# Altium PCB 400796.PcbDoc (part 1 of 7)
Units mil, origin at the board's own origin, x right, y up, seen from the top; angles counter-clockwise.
Board outline 2086.61 x 2086.61 mil, 6 copper layers (Top Layer, Mid Layer 1, Mid Layer 2, Mid Layer 3, Mid Layer 4, Bottom Layer), stack 58.818 mil thick; 313 components, 234 nets, 1244 pads, 2538 vias.
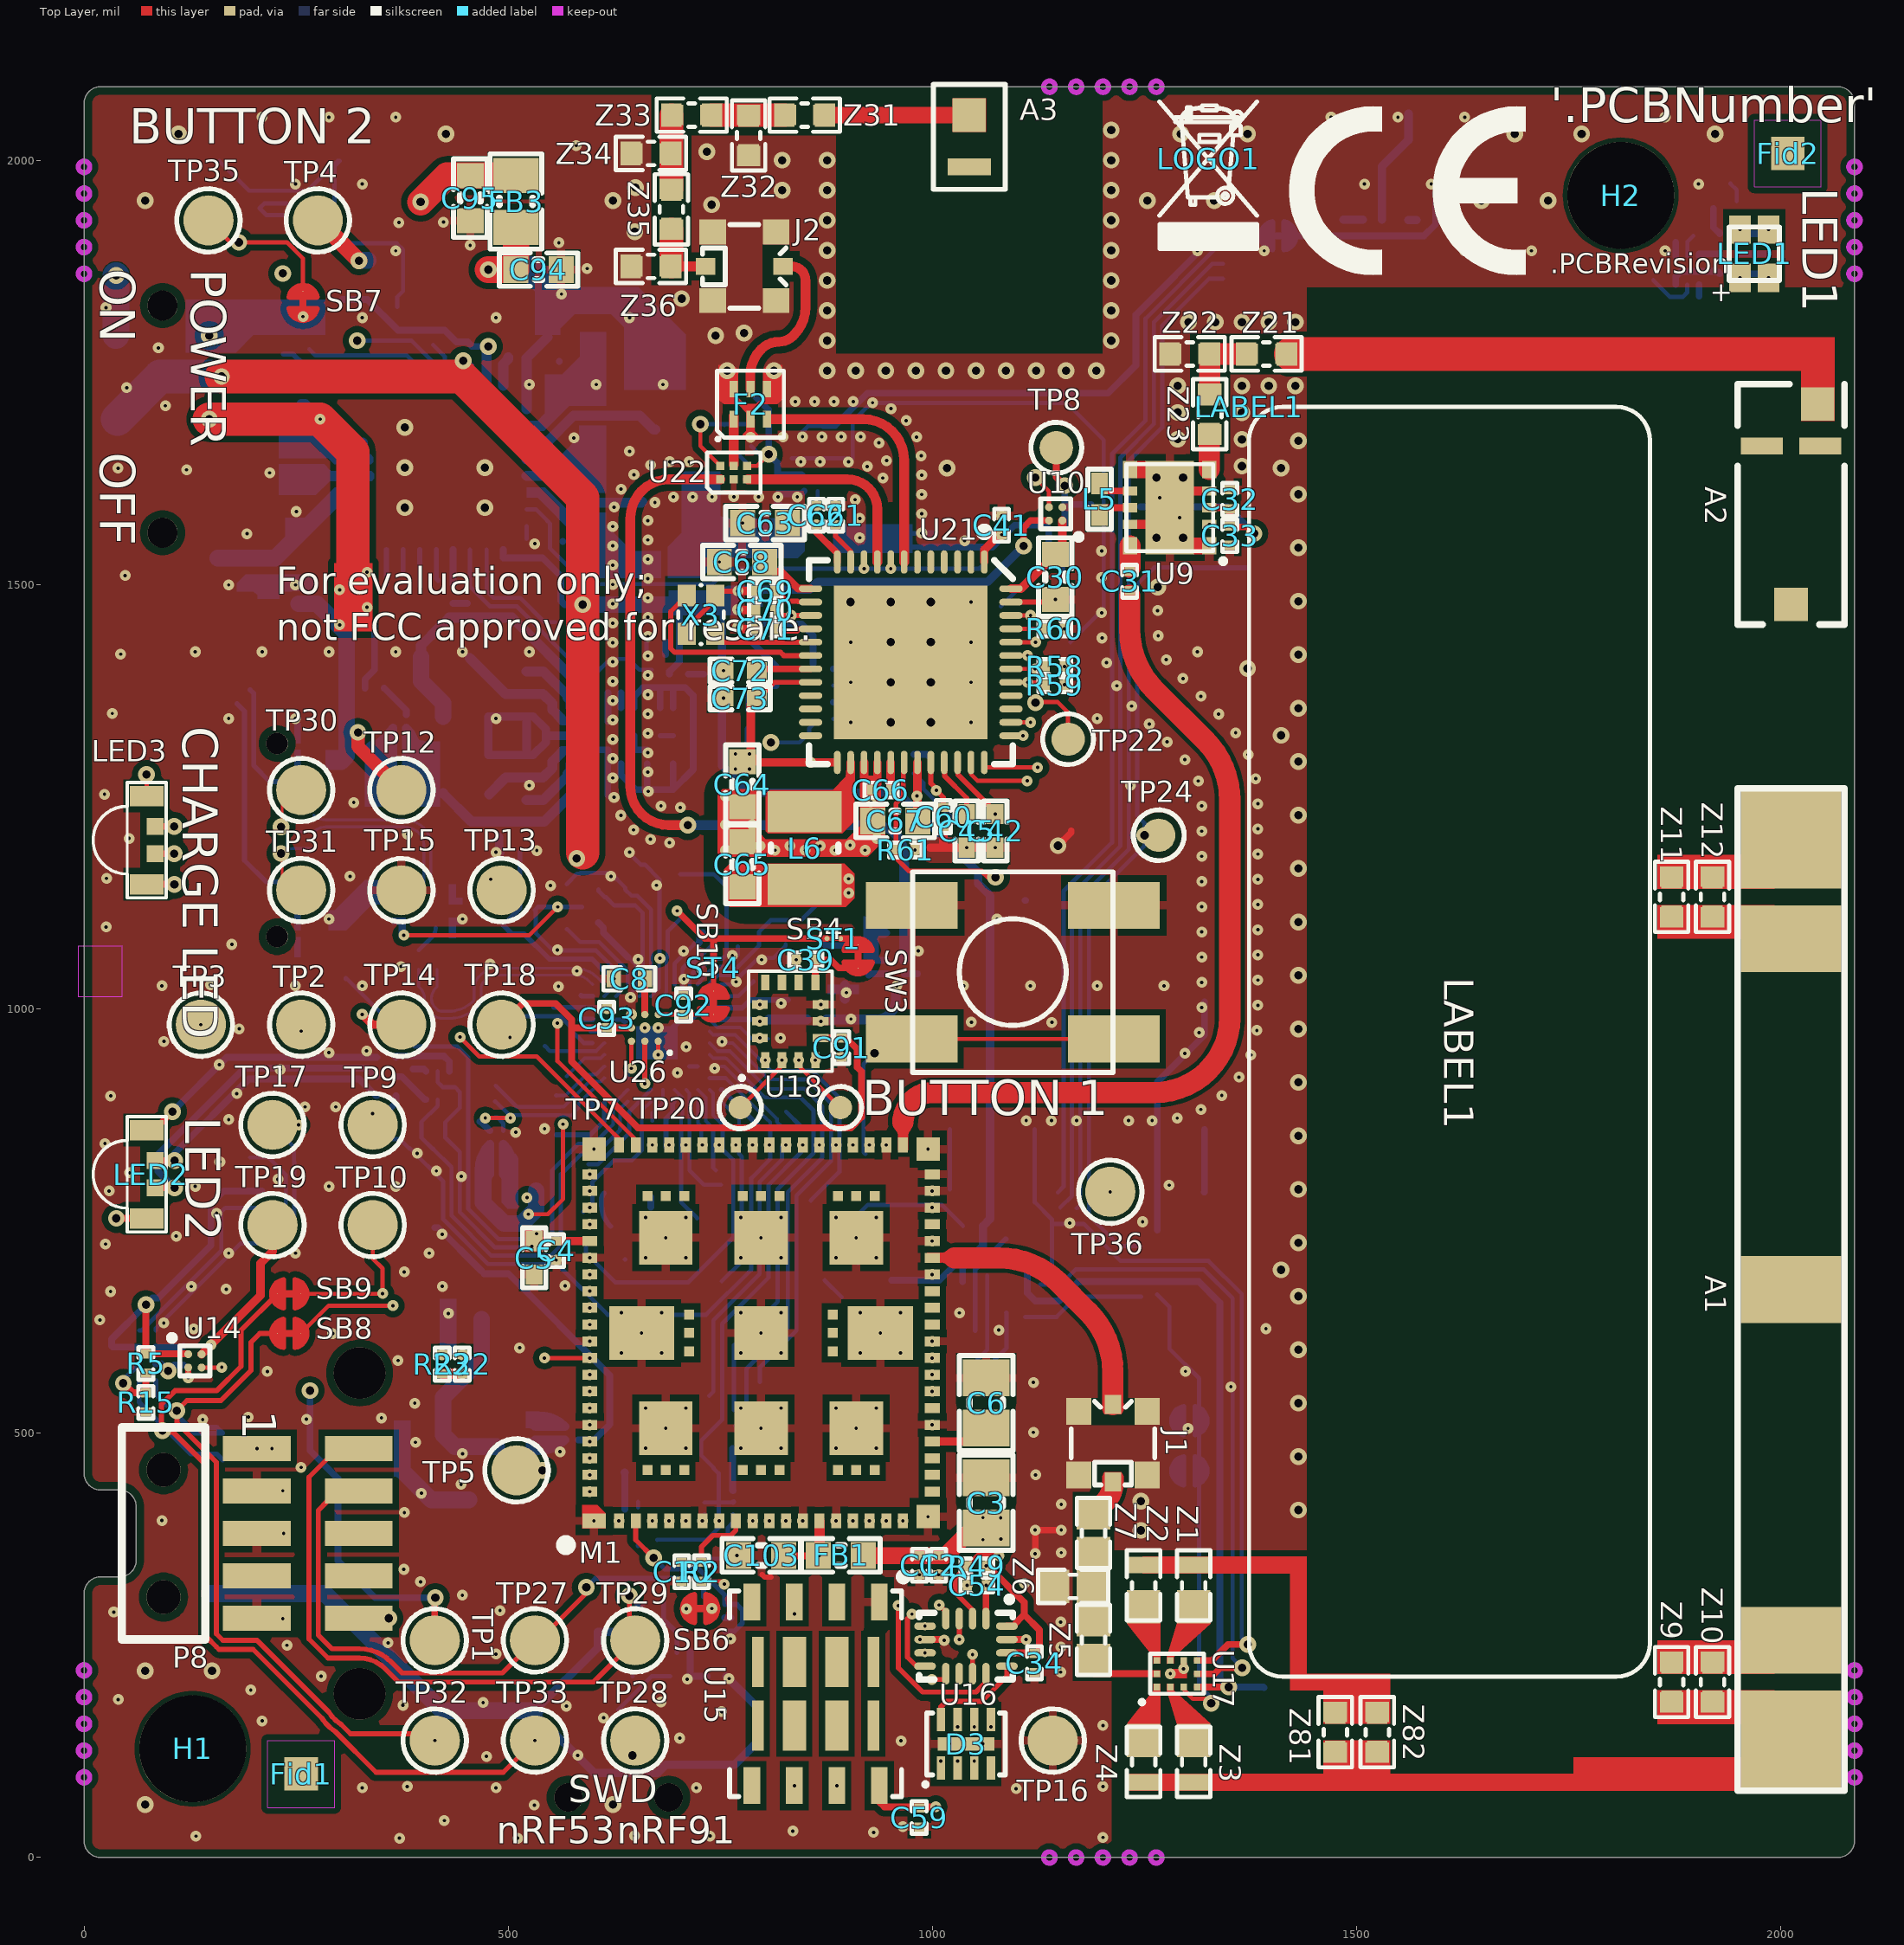
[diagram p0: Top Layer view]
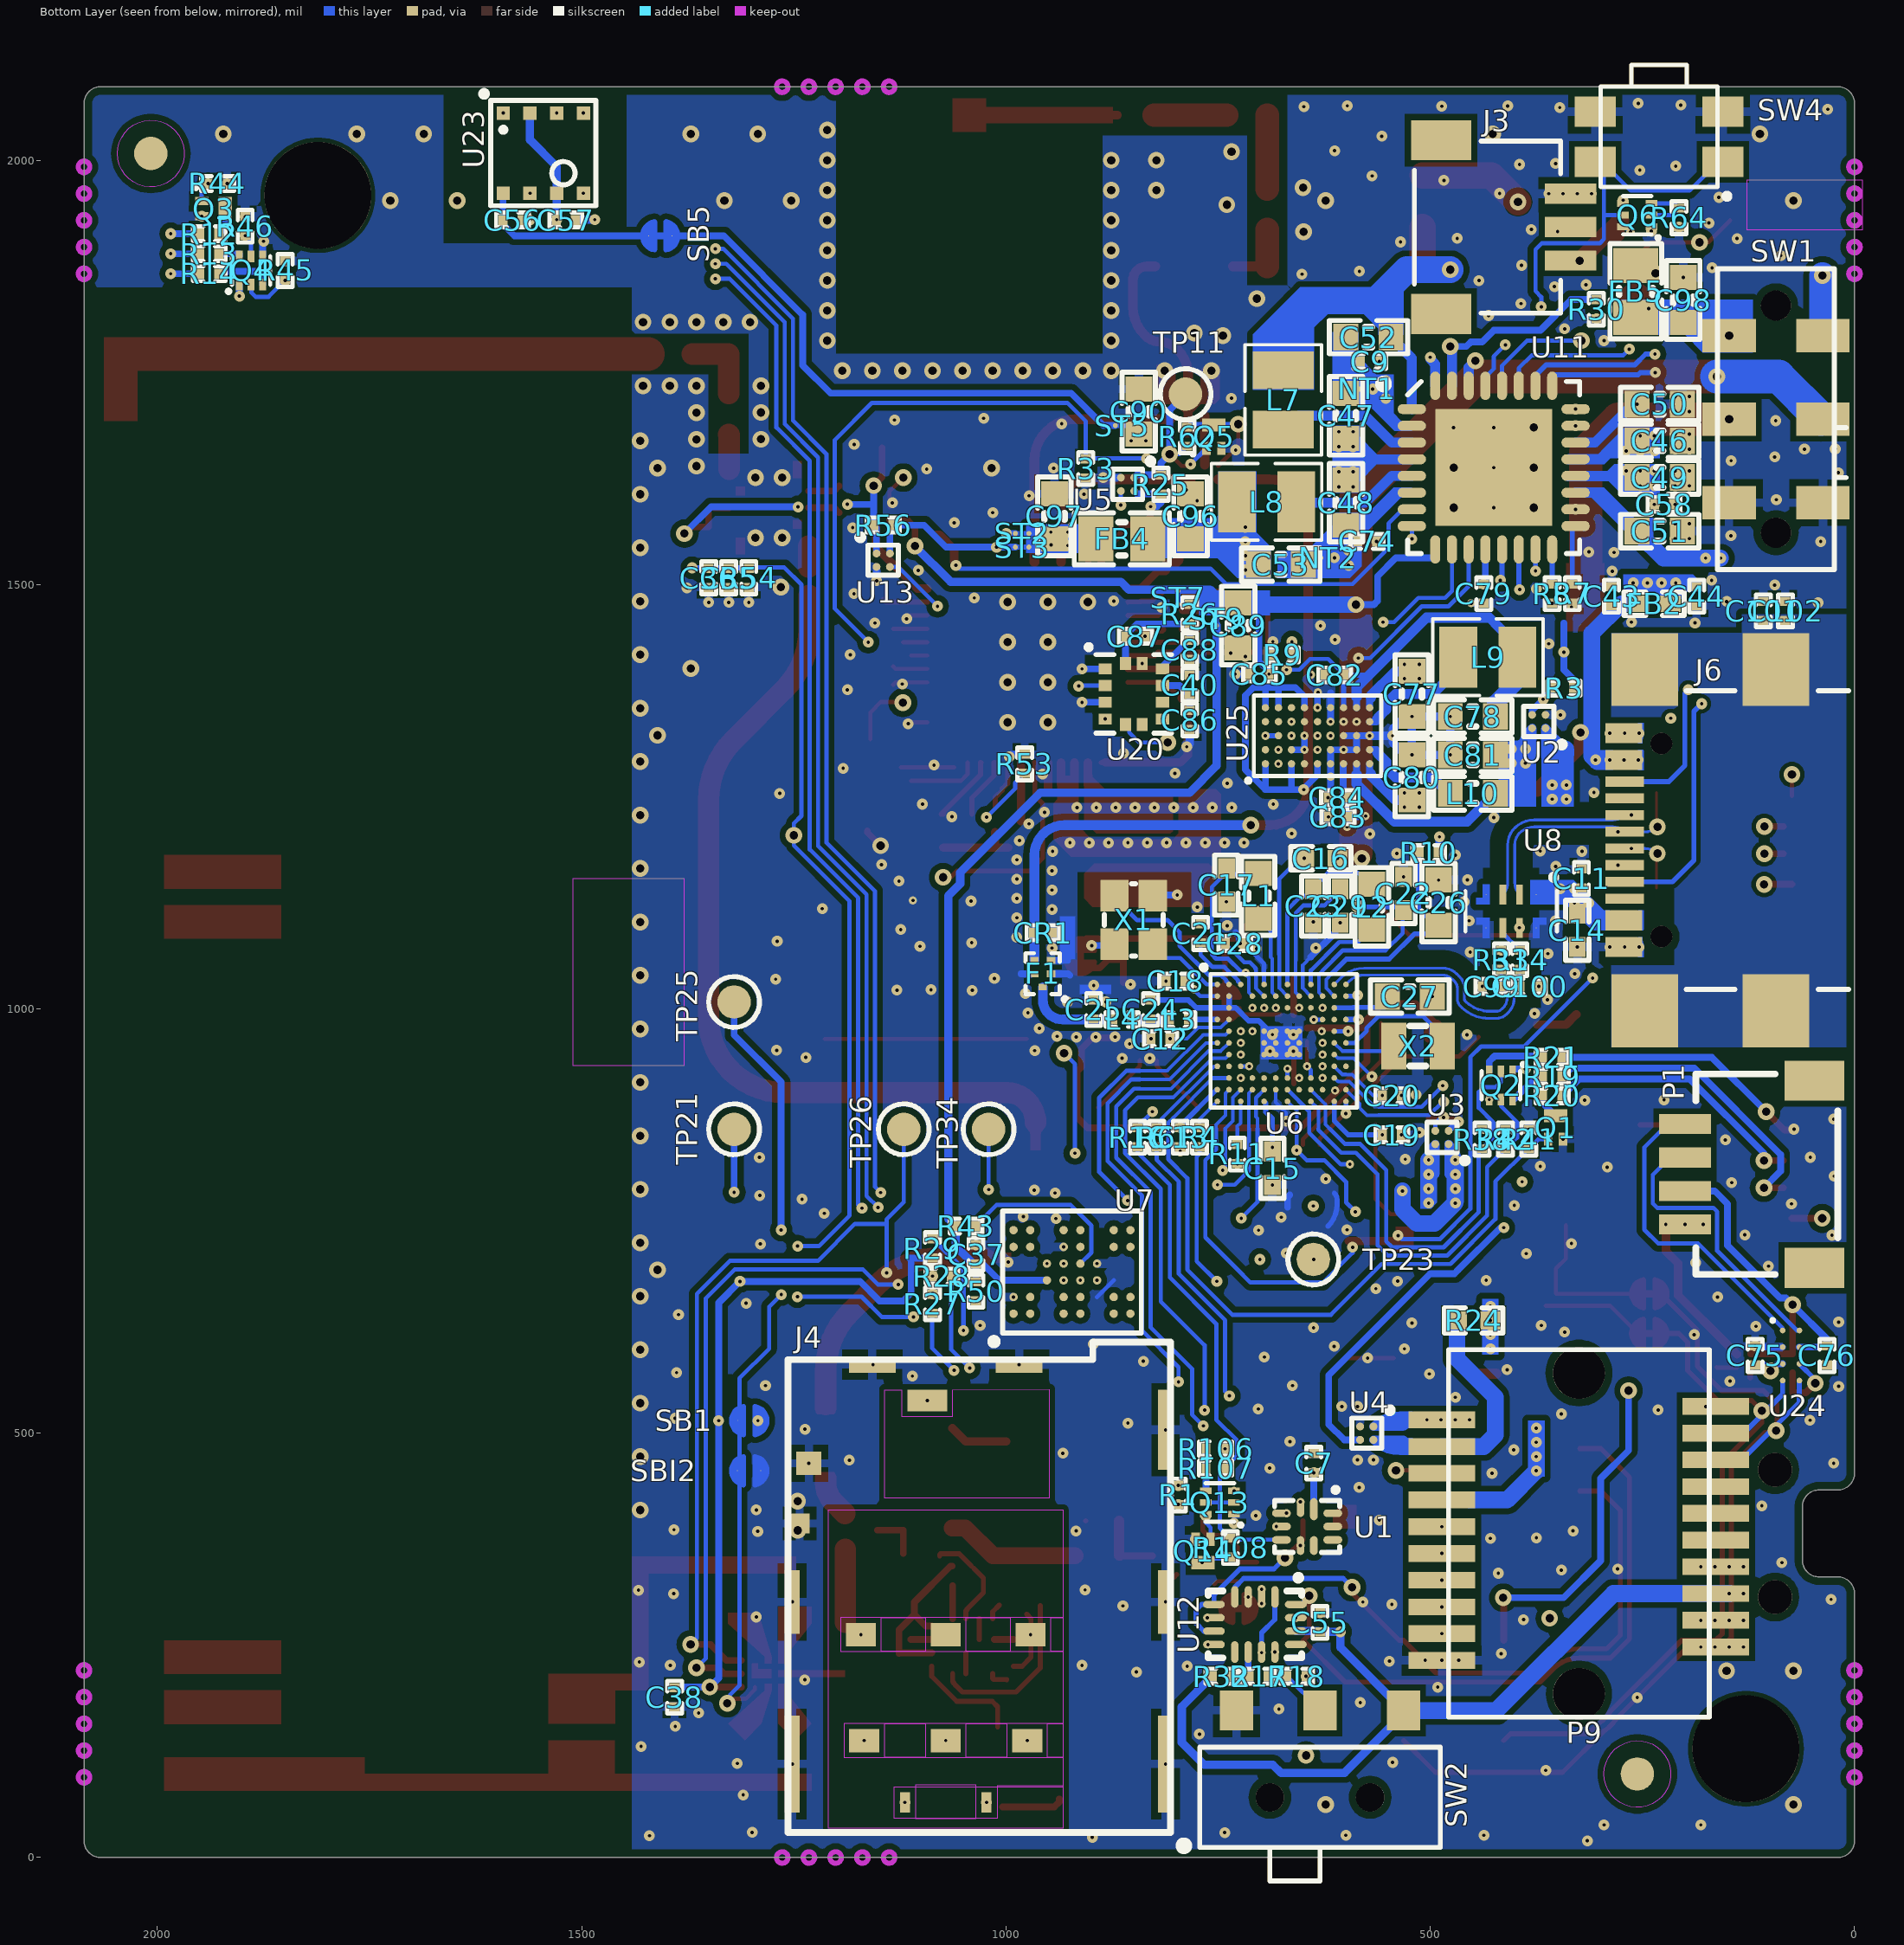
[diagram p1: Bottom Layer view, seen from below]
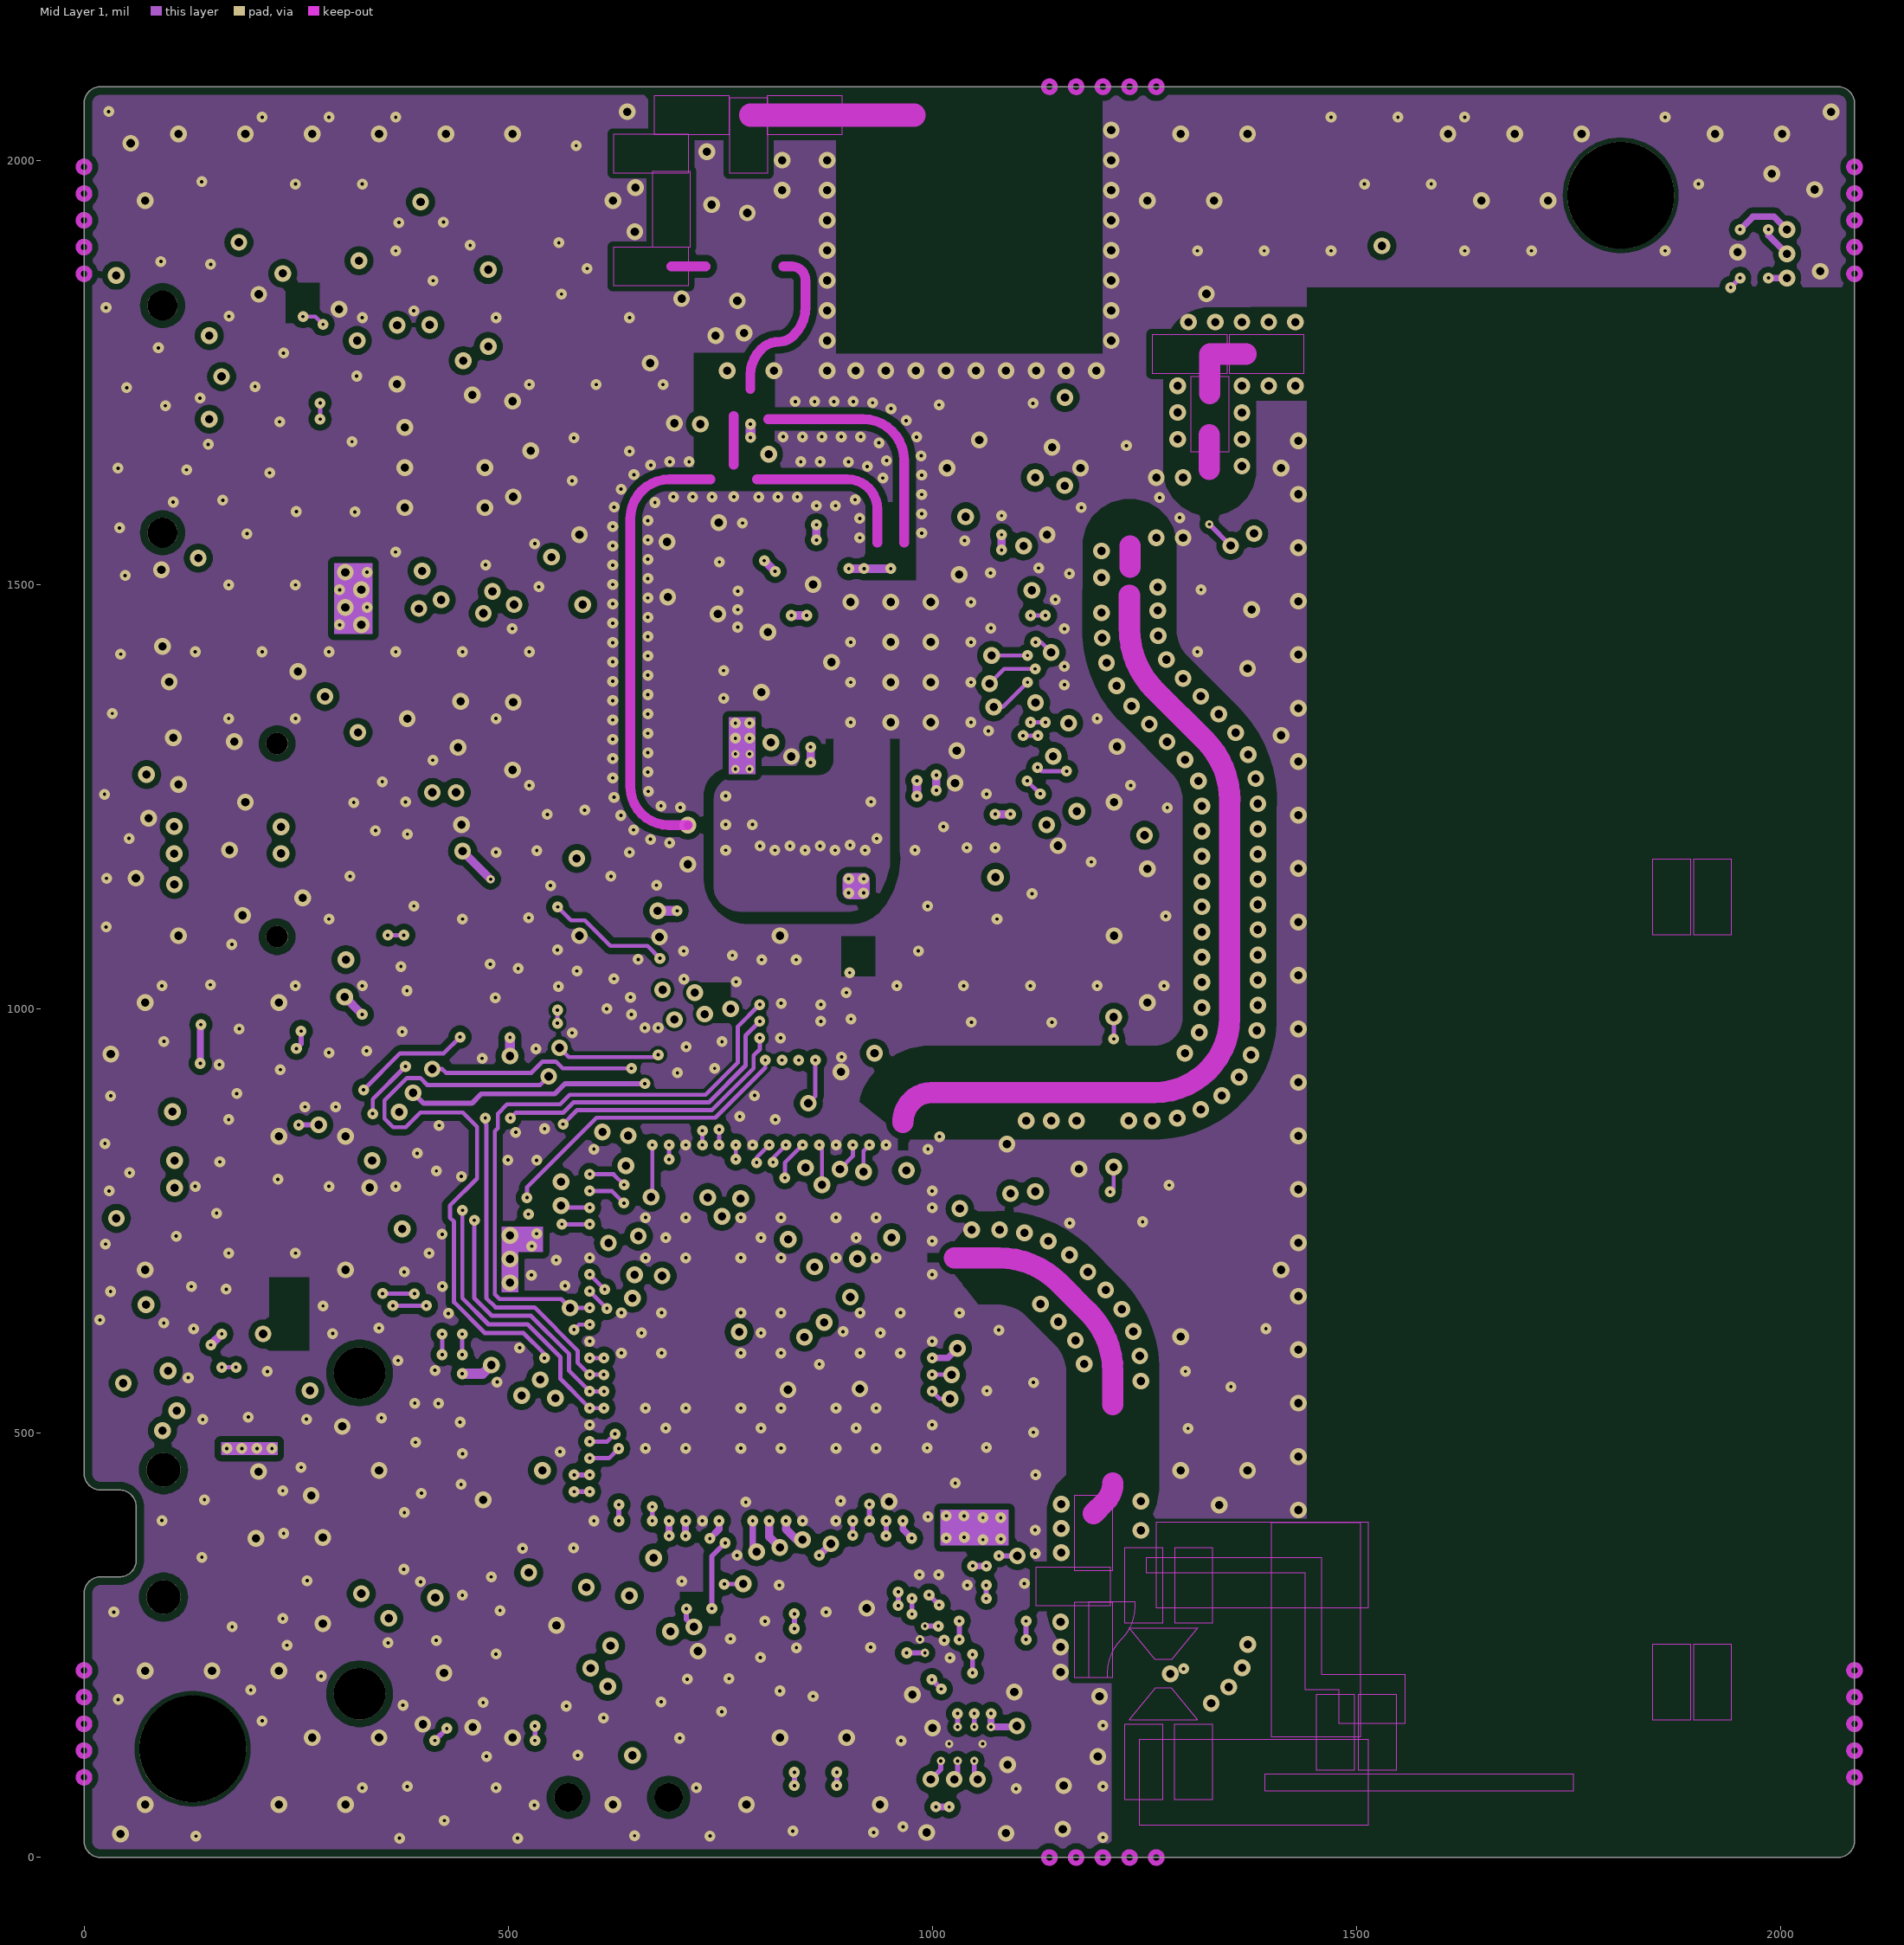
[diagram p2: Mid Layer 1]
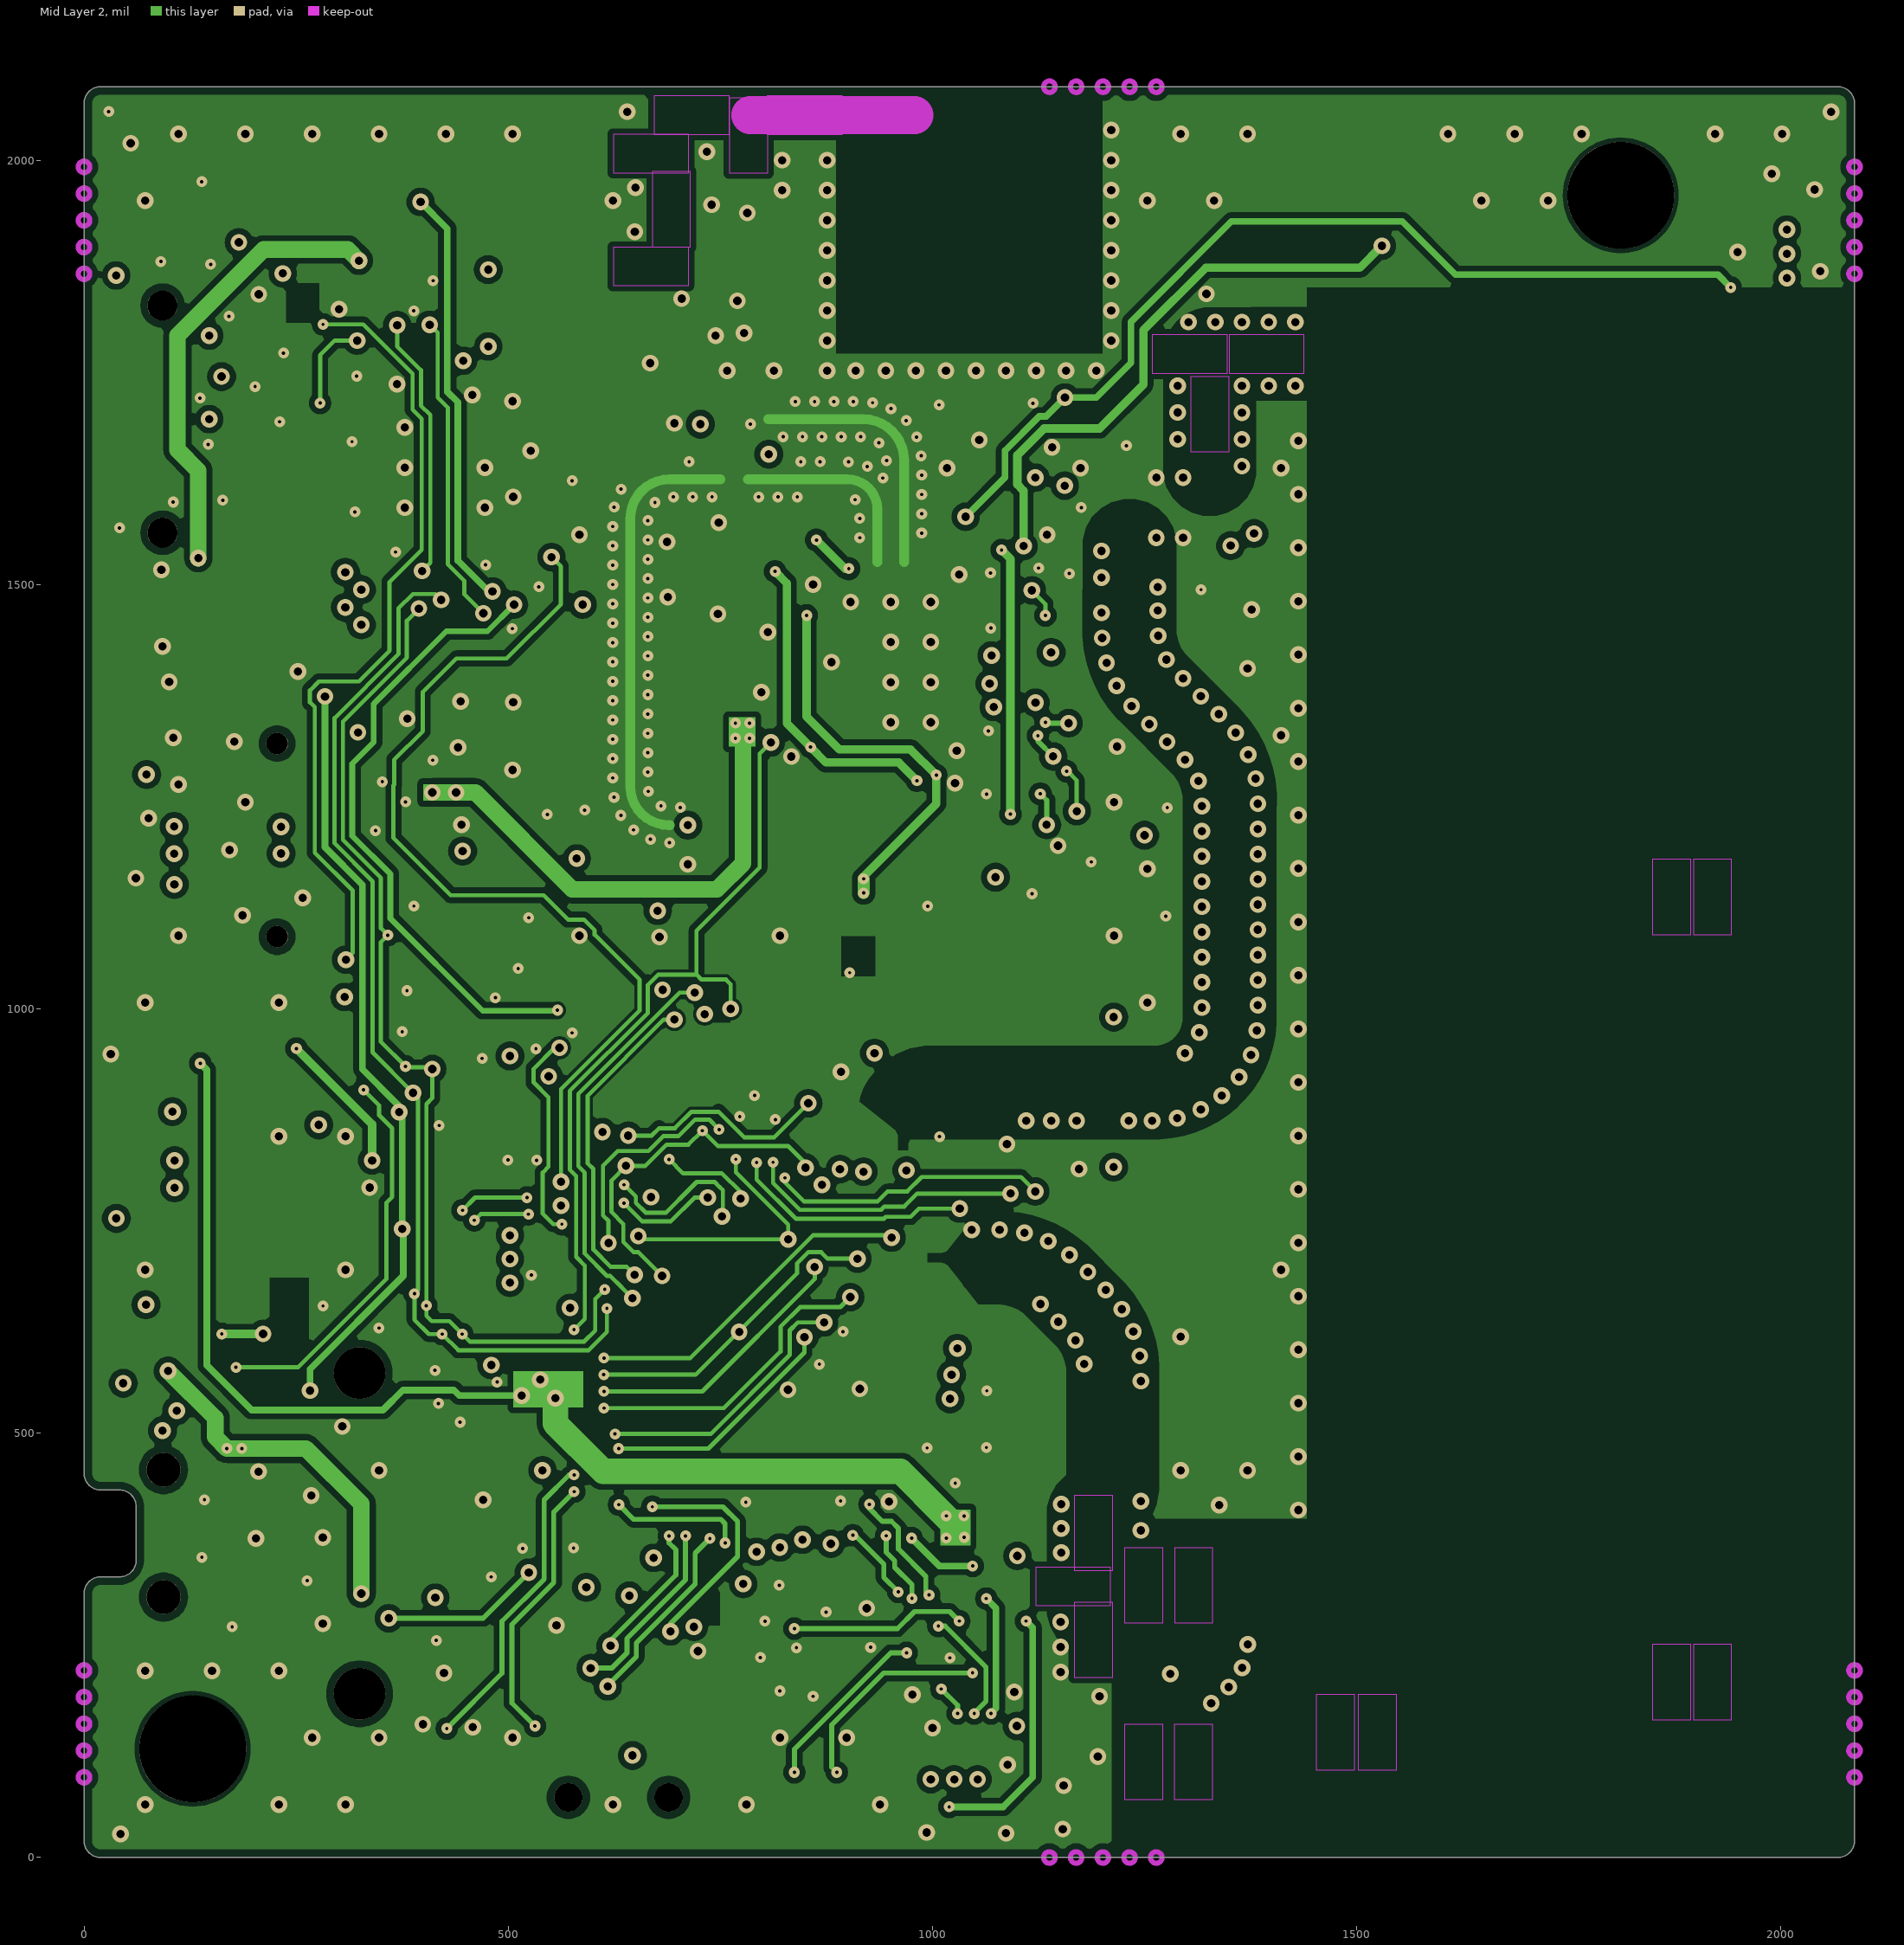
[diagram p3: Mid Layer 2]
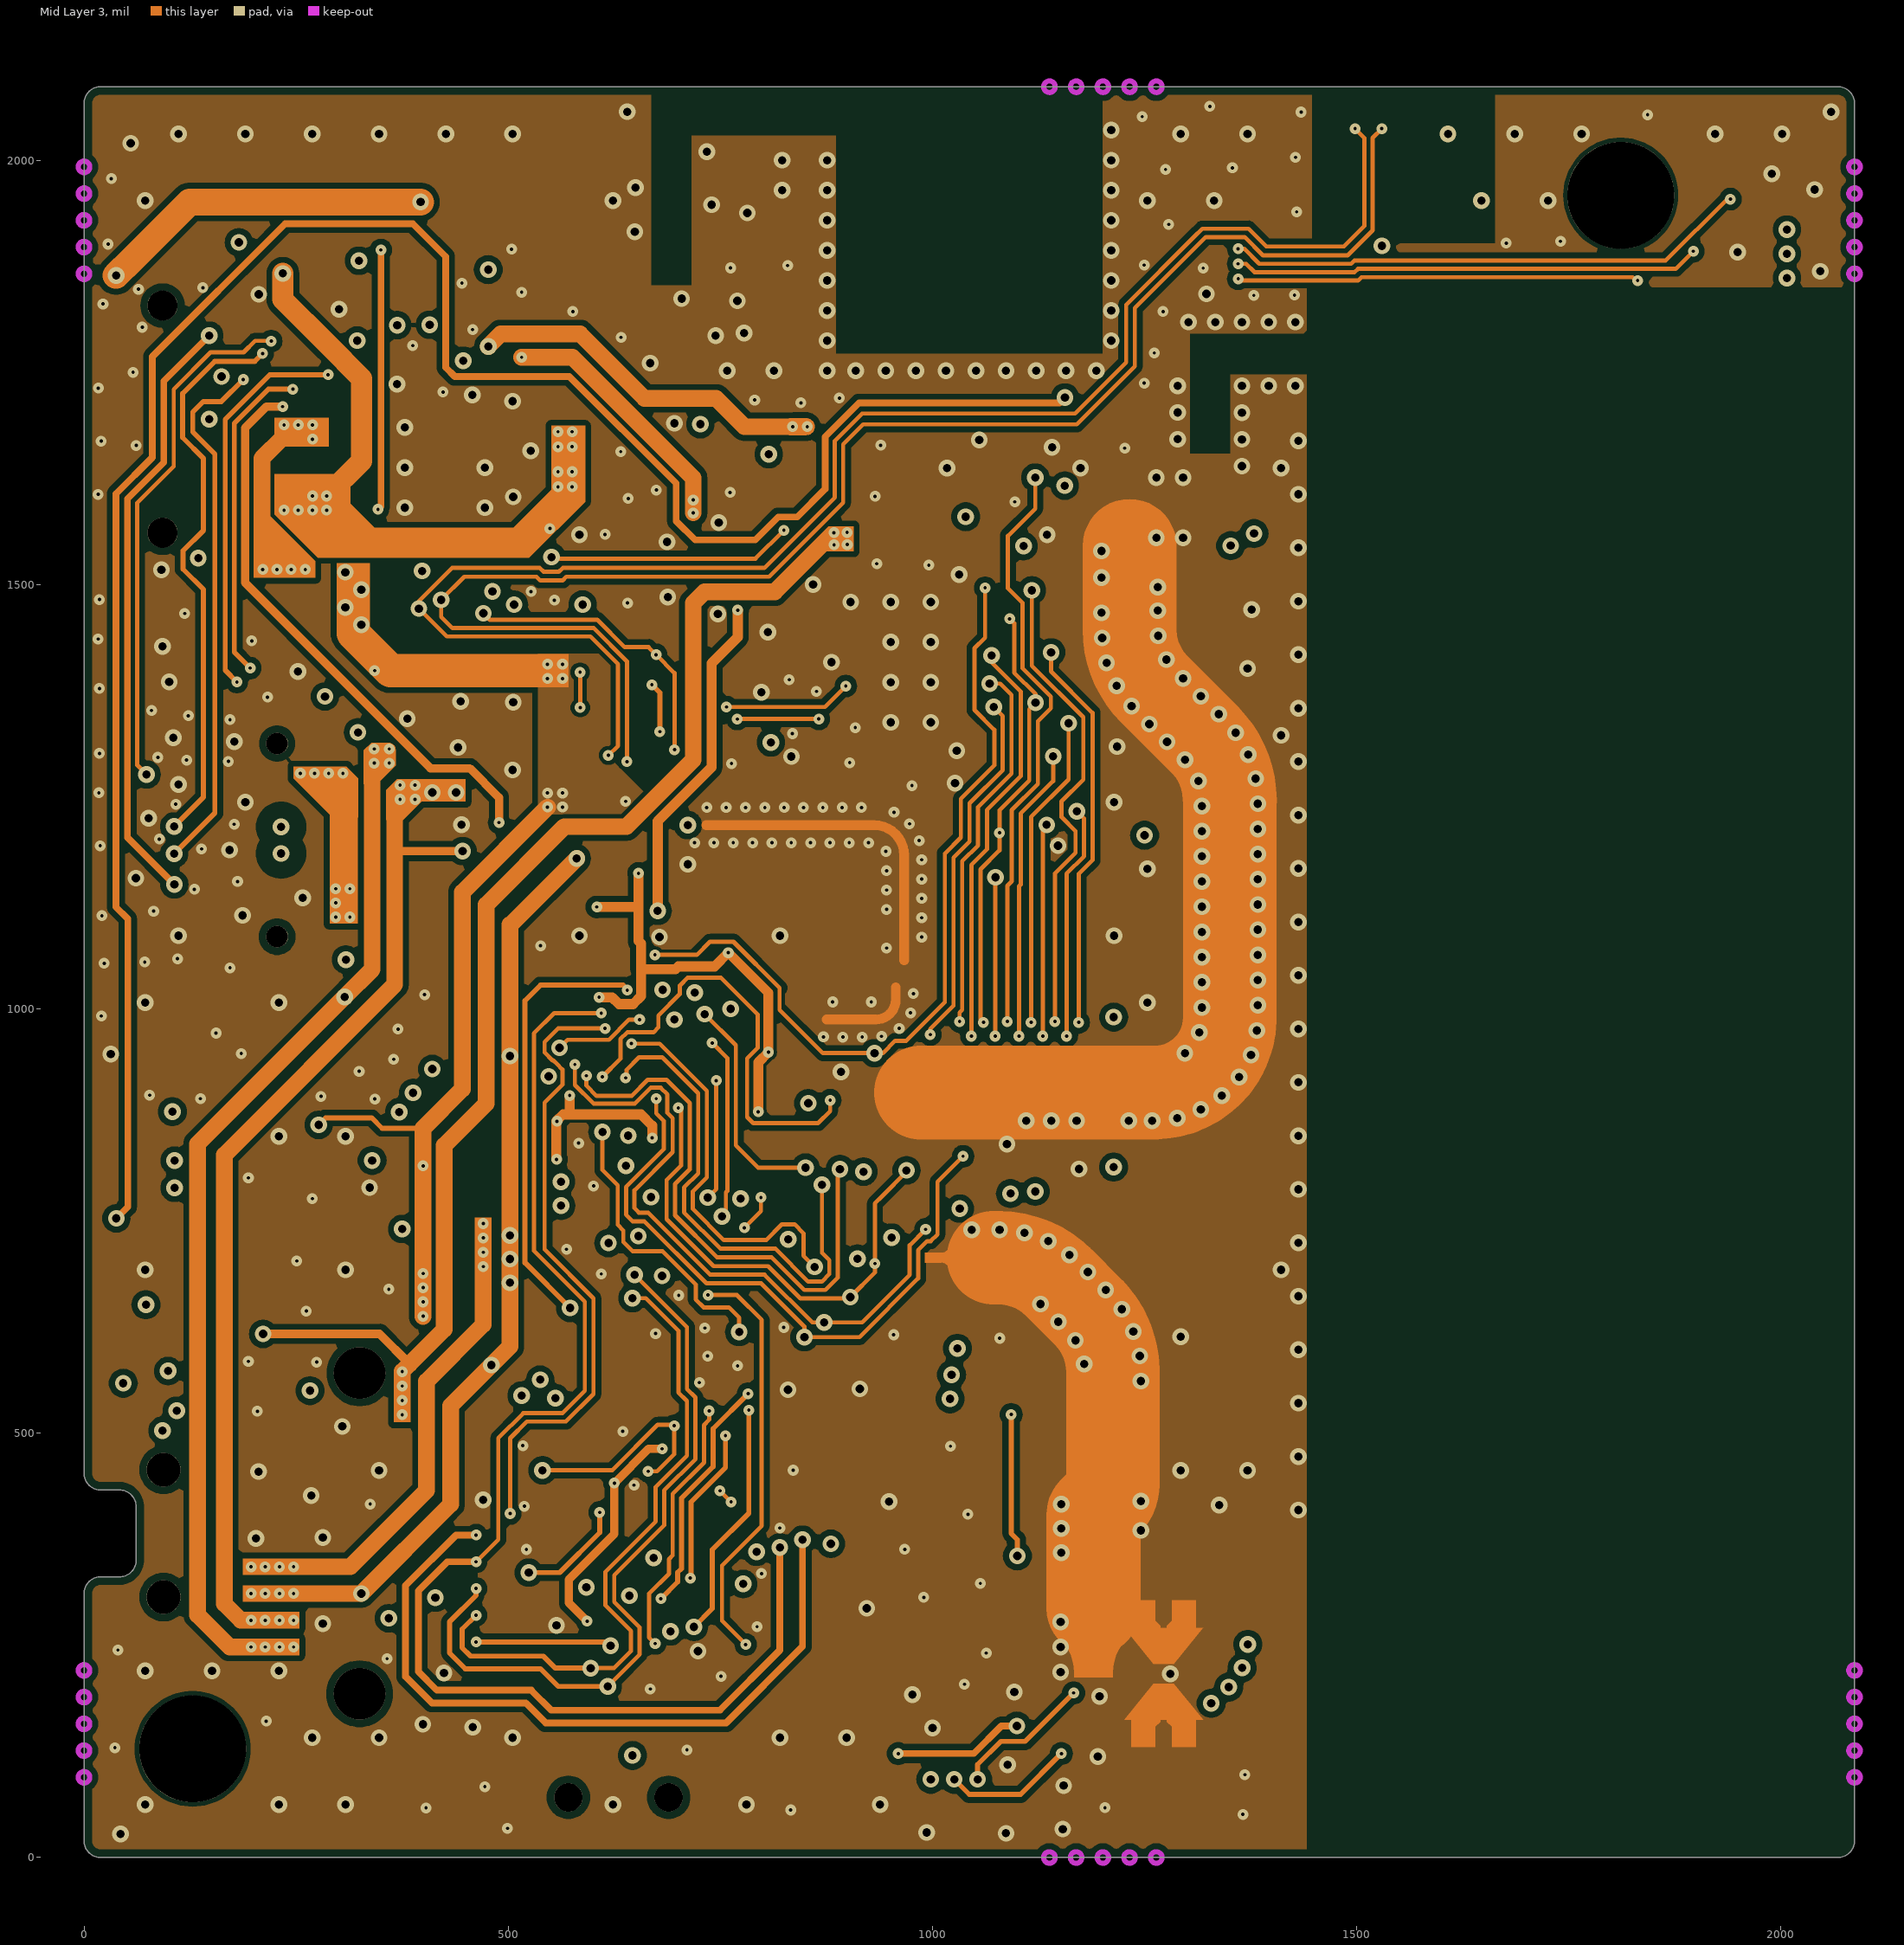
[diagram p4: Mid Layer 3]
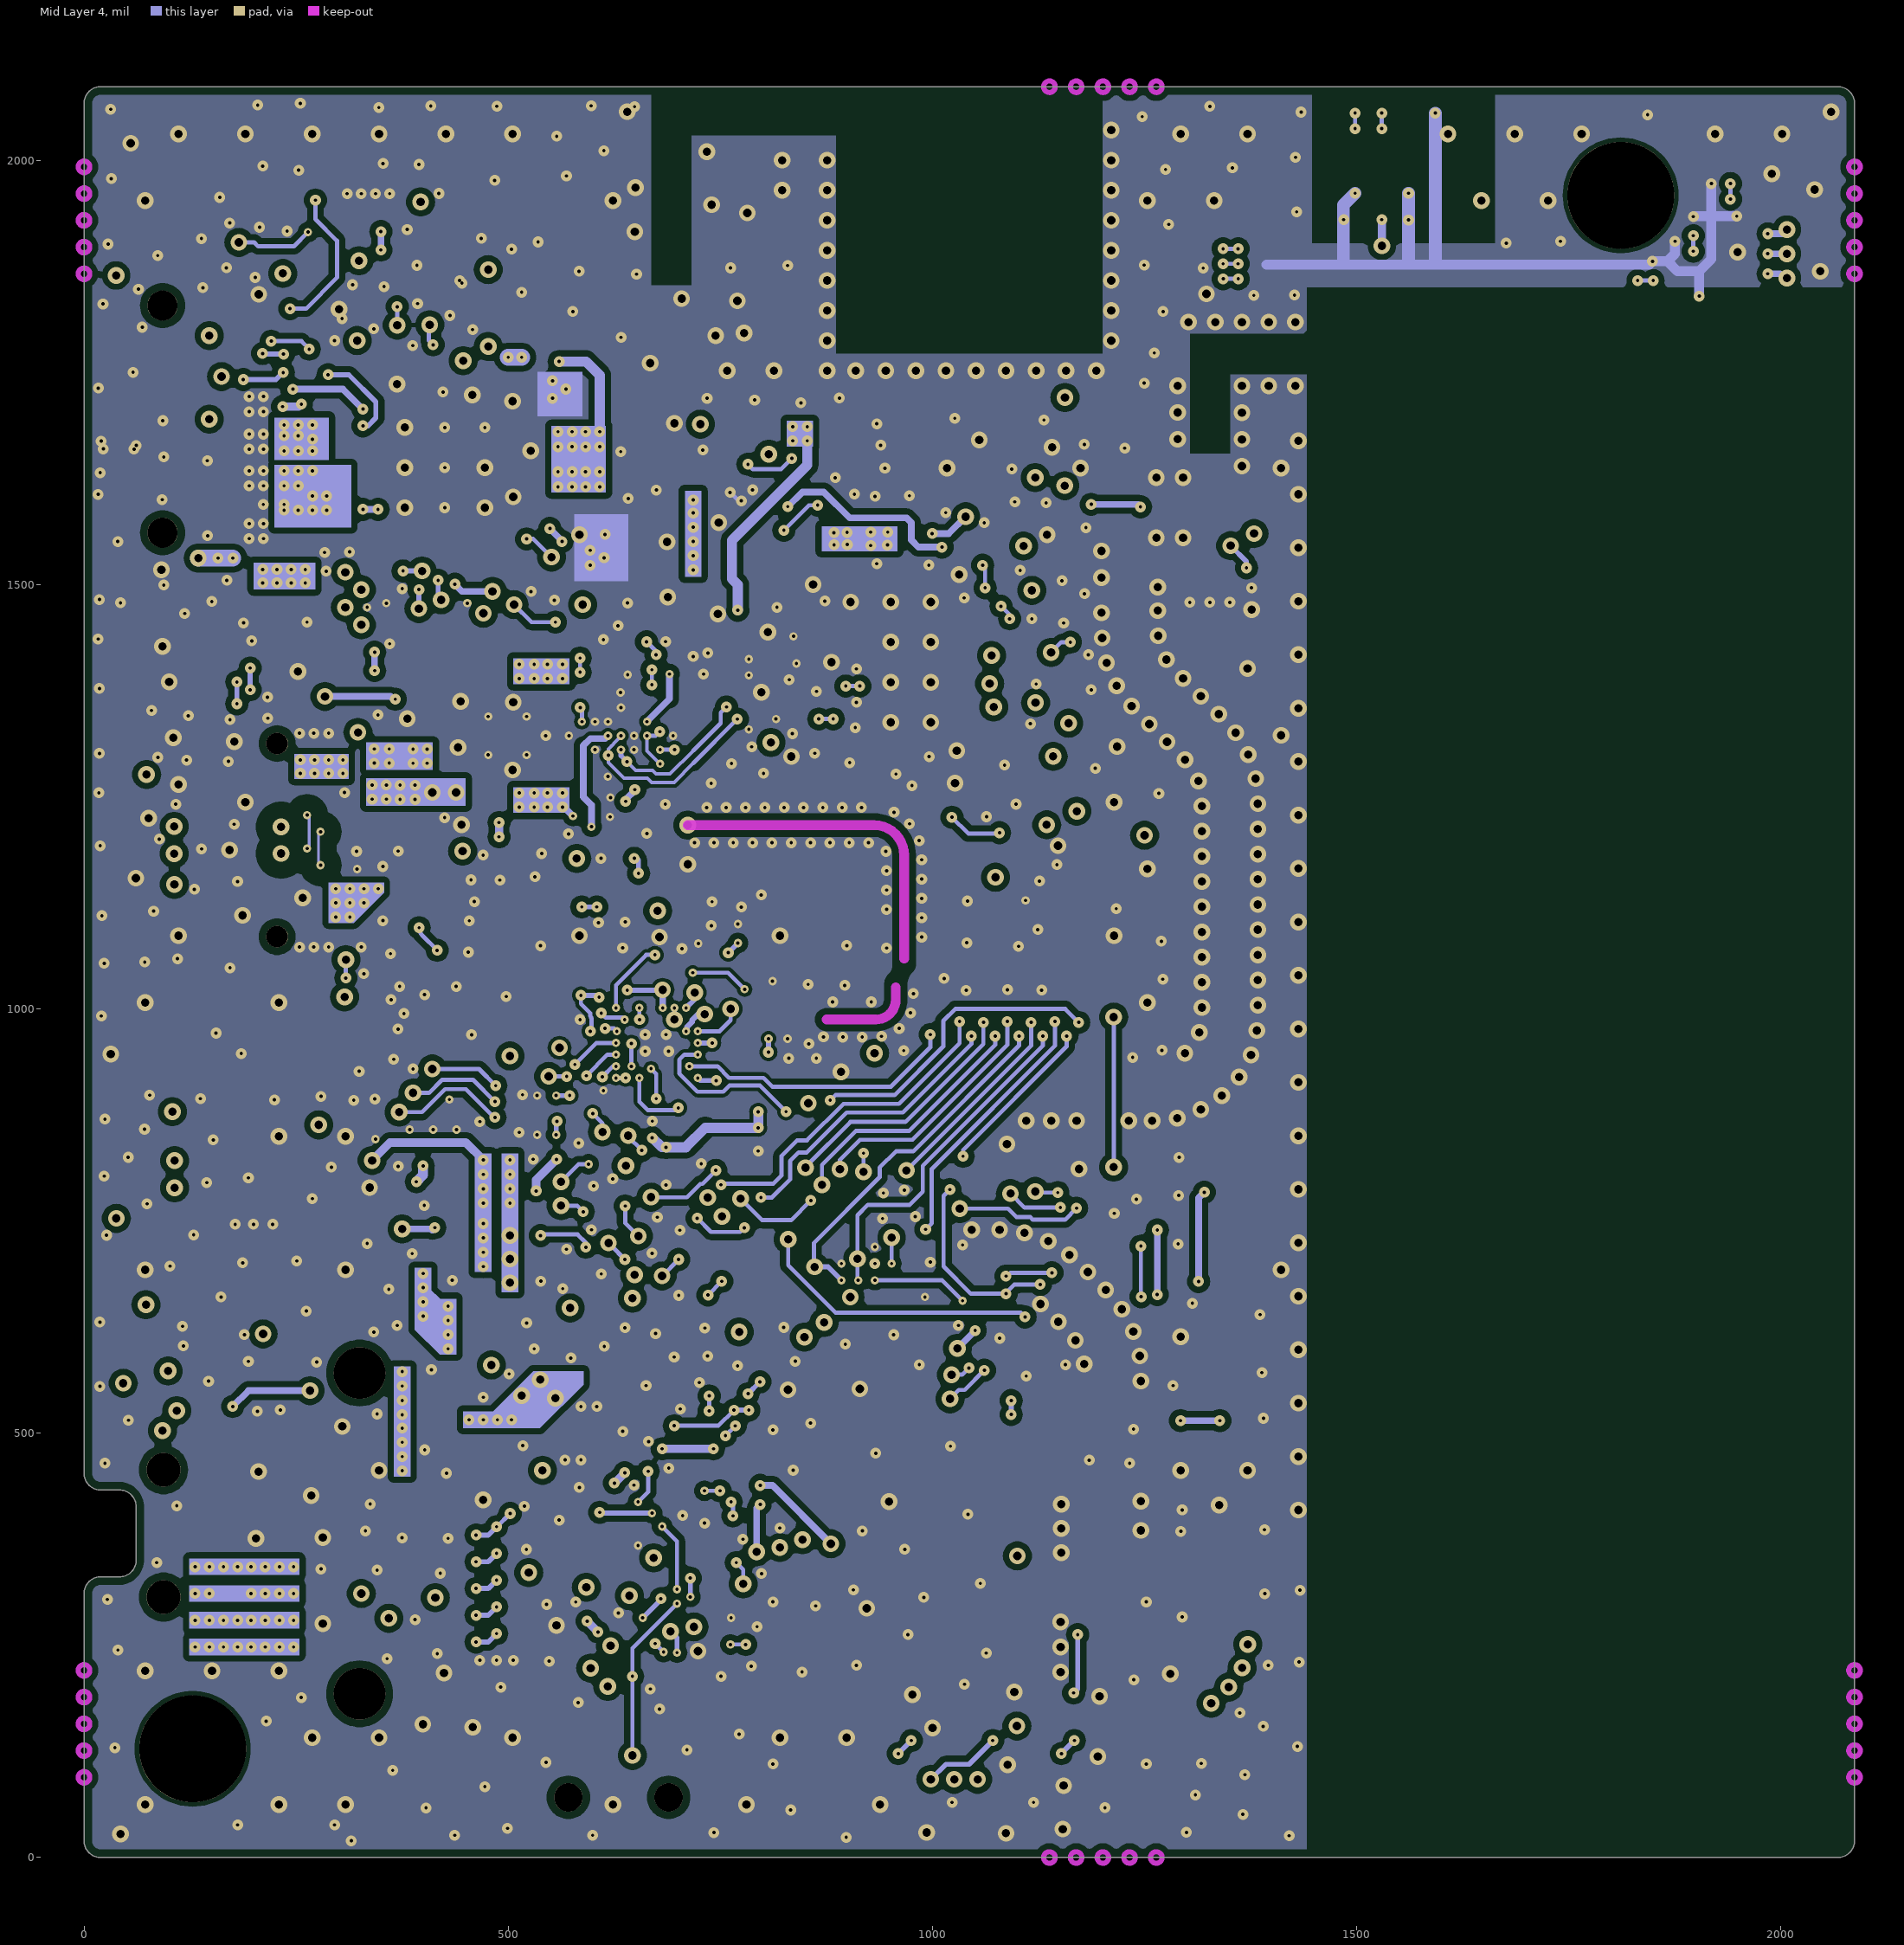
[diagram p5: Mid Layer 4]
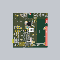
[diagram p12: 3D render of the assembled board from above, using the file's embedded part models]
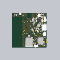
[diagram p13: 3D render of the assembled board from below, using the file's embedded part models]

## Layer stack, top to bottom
Top Solder: solder mask 1.969, Solder Resist Halogen-Free, Dk 3.5
Top Layer: signal copper 1.378
Dielectric1: prepreg 2.795, FR-4 Halogen-Free, Dk 4.2
Mid Layer 1: signal copper 1.378
Dielectric 3: prepreg 2.795, FR-4 Halogen-Free, Dk 4.2
Mid Layer 2: signal copper 1.378
Dielectric 2: core 39.37, Dk 4.51
Mid Layer 3: signal copper 1.378
Dielectric 1: prepreg 2.795, FR-4 Halogen-Free, Dk 4.2
Mid Layer 4: signal copper 1.378
Dielectric 4: prepreg 2.795, FR-4 Halogen-Free, Dk 4.2
Bottom Layer: signal copper 1.378
Bottom Solder: solder mask 1.969, Solder Resist Halogen-Free, Dk 3.5

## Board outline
0,19.69 ccw(c19.68,19.69) 19.68,0 2066.93,0 ccw(c2066.93,19.69) 2086.61,19.69 2086.61,2066.93 ccw(c2066.93,2066.93) 2066.93,2086.61 19.68,2086.61 ccw(c19.68,2066.93) 0,2066.93 0,452.75 ccw(c19.68,452.75) 19.68,433.07 41.73,433.07 cw(c41.73,413.38) 61.42,413.38 61.42,350.39 cw(c41.73,350.39) 41.73,330.71 19.69,330.71 ccw(c19.69,311.02) 0,311.02

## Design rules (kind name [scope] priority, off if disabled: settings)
BoardOutlineClearance BoardOutlineClearance_Power_SW [HasFootprint('Switch-Slide-RA-J-Lead-DPDT-8.5x3.5mm')] p1: gap=5.91 ignorepadtopadclearanceinfootprint=FALSE
BoardOutlineClearance [(OnLayer('Top Layer') or OnLayer('Bottom Layer') or OnLayer('Mid Layer 1') or OnLayer('Mid Layer 2') or OnLayer('Mid Layer 3') or OnLayer('Mid Layer 4')) and not Keepout] p2: gap=9.45 ignorepadtopadclearanceinfootprint=FALSE
Clearance Clearance_NPTH [InPadClass('NPTH')] p1: gap=5 ignorepadtopadclearanceinfootprint=FALSE
Clearance "Schematic Clearance Constraint_1" [InComponent('H2')] p2: gap=10 ignorepadtopadclearanceinfootprint=TRUE except(0: Arc-Hole Track-Hole SMDPad-Hole THPad-Hole Via-Hole Fill-Hole Poly-Hole Region-Hole Text-Hole)
Clearance "Schematic Clearance Constraint" [InComponent('H1')] p3: gap=10 ignorepadtopadclearanceinfootprint=TRUE except(0: Arc-Hole Track-Hole SMDPad-Hole THPad-Hole Via-Hole Fill-Hole Poly-Hole Region-Hole Text-Hole)
Clearance "Stitching GND blind" [IsStitchingVia and (InDrillLayerPair('Top Layer - Mid Layer 1') or InDrillLayerPair('Mid Layer 4 - Bottom Layer')) and InNet('GND') vs (IsVia and InDrillLayerPair('Top Layer - Bottom Layer')) Or IsPad] p4: gap=39.37 ignorepadtopadclearanceinfootprint=FALSE
Clearance "Stitching GND" [IsStitchingVia and InNet('GND') vs IsVia Or IsPad] p5: gap=9.84 ignorepadtopadclearanceinfootprint=FALSE
Clearance Clearance_nRF5340 [All vs WithinRoom('nRF53')] p6: gap=3.94 ignorepadtopadclearanceinfootprint=FALSE
Clearance Clearance_nPM6001 [OnLayer('Mid Layer 4') vs WithinRoom('nPM6001')] p7: gap=4.13 ignorepadtopadclearanceinfootprint=FALSE
Clearance USB_Poly_Clearance [(InNamedPolygon('Top Layer-GND')) or (InNamedPolygon('Mid_Layer_1_Codec-GND')) or (InNamedPolygon('Mid_Layer_3-GND')) or (InNamedPolygon('Mid_Layer_3-GND')) or (InNamedPolygon('Mid_Layer_4-GND')) or (InNamedPolygon('Mid_Layer_1-AGND') or InNamedPolygon('Bottom_Layer-GND')) vs InAnyDifferentialPair] p8: gap=19.68 ignorepadtopadclearanceinfootprint=FALSE
Clearance "Diff_Pair_Clearance_Other _Diffpair" [InAnyDifferentialPair and (IsArc or IsTrack)] p9: gap=11.8 ignorepadtopadclearanceinfootprint=FALSE
Clearance Diff_Pair_Clearance_Not_Diffpair [InAnyDifferentialPair and (IsArc or IsTrack) vs not InAnyDifferentialPair] p10: gap=4.92 ignorepadtopadclearanceinfootprint=FALSE
Clearance Microvia_Clearance [AsMM(ViaDiameter) = 0.3 vs AsMM(ViaDiameter) = 0.3] p11: gap=3.94 ignorepadtopadclearanceinfootprint=FALSE
Clearance "NPTH clearance_MIC" [(Not PadIsPlated And HoleSize > 0) and (InRegionRelative(100,1032,150,1092) or InRegionRelative(1000,1952,1050,2002))] p12: gap=3.94 ignorepadtopadclearanceinfootprint=FALSE
Clearance "NPTH clearance" [Not PadIsPlated And HoleSize > 0] p13: gap=8.66 ignorepadtopadclearanceinfootprint=FALSE
Clearance RF_Clerance [InNetClass('RF')] p14: gap=4.92 ignorepadtopadclearanceinfootprint=FALSE
Clearance RF_Clerance_RF_BLE/WIFI [InNetClass('RF_BLE/WIFI') vs InNamedPolygon('Top_Layer-GND') or InNamedPolygon('Bottom_Layer-GND')] p15: gap=7.87 ignorepadtopadclearanceinfootprint=FALSE
Clearance Polygon_Clearance_Codec [InNamedPolygon('Mid_Layer_1_Codec-GND')] p16: gap=4.92 ignorepadtopadclearanceinfootprint=FALSE
Clearance Polygon_Clearance [(InNamedPolygon('Top_Layer-GND')) or (InNamedPolygon('Mid_Layer_1-GND')) or (InNamedPolygon('Mid_Layer_2-GND')) or (InNamedPolygon('Mid_Layer_3-GND')) or (InNamedPolygon('Mid_Layer_4-GND')) or (InNamedPolygon('Mid_Layer_4-AGND') or InNamedPolygon('Bottom_Layer-GND'))] p17: gap=7.09 ignorepadtopadclearanceinfootprint=FALSE
Clearance [All] p18: gap=4.92 ignorepadtopadclearanceinfootprint=FALSE
ComponentClearance [All] p1 off: gap=10 collisioncheckmode=3 verticalgap=10 showdistances=FALSE
DiffPairsRouting [InAnyDifferentialPair] p1: maxlimit=5 minlimit=5 mostfreqgap=5 toplayer_minwidth=3.27 toplayer_maxwidth=3.27 toplayer_prefwidth=3.27 midlayer1_minwidth=1.63 midlayer1_maxwidth=1.63 midlayer1_prefwidth=1.63 midlayer2_minwidth=2.31 midlayer2_maxwidth=2.31 midlayer2_prefwidth=2.31 midlayer3_minwidth=2.31 midlayer3_maxwidth=2.31 midlayer3_prefwidth=2.31 midlayer4_minwidth=1.63 midlayer4_maxwidth=1.63 midlayer4_prefwidth=1.63 bottomlayer_minwidth=3.27 bottomlayer_maxwidth=3.27 bottomlayer_prefwidth=3.27 impedanceprofiledriven=TRUE impedanceprofileid={B73BED5C-2360-4F1A-9E9C-C8917F192C1F} impedanceprofilevalue=90.000000 maxuncoupledlength=500
FabricationTestPointUsage TestPointUsage [All] p1: valid=0 allowmultiple=FALSE
FabricationTestpoint Testpoint [All] p1: side=3 testpointundercomponent=TRUE minsize=40 maxsize=100 preferedsize=60 minholesize=0 maxholesize=40 preferedholesize=32 testpointgrid=1 allowsidetop=TRUE allowsidebottom=TRUE usegrid=TRUE gridtolerance=0.01
Height [All] p1 off: minheight=0 maxheight=1000 prefheight=500
HoleSize HoleSize_Laser_Via [IsVia and (InDrillLayerPair('Top Layer - Mid Layer 1') or InDrillLayerPair('Mid Layer 1 - Mid Layer 2') or InDrillLayerPair('Mid Layer 3 - Mid-Layer 4') or InDrillLayerPair('Mid Layer 4 - Bottom Layer'))] p1: absolutevalues=TRUE maxlimit=3.94 minlimit=3.94 maxpercent=80.000 minpercent=20.000
HoleSize HoleSize_Mech_Via [IsVia and (InDrillLayerPair('Top Layer - Bottom Layer') or InDrillLayerPair('Mid Layer 1 - Mid Layer 4'))] p2: absolutevalues=TRUE maxlimit=9.84 minlimit=9.84 maxpercent=80.000 minpercent=20.000
HoleSize [All] p3: absolutevalues=TRUE maxlimit=196.85 minlimit=3.94 maxpercent=80.000 minpercent=20.000
HoleToHoleClearance HoleToHoleClearance_PMIC [InDrillLayerPair('Mid Layer 4 - Bottom Layer') and InRegionRelative(580,1280,700,1350) vs InDrillLayerPair('Mid Layer 4 - Bottom Layer') and InRegionRelative(580,1280,700,1350)] p1: gap=11.42 allowstackedmicrovias=FALSE
HoleToHoleClearance HoleToHoleClearance_T-B_T-B [InDrillLayerPair('Top Layer - Bottom Layer') vs InDrillLayerPair('Top Layer - Bottom Layer')] p2 off: gap=17.72 allowstackedmicrovias=FALSE
HoleToHoleClearance HoleToHoleClearance_TH-TH [AsMM(ViaDiameter) = 0.50 vs AsMM(ViaDiameter) = 0.50] p3: gap=17.72 allowstackedmicrovias=FALSE
HoleToHoleClearance HoleToHoleClearance_TH-Micro [AsMM(ViaDiameter) = 0.50 vs AsMM(ViaDiameter) = 0.30] p4: gap=17.72 allowstackedmicrovias=FALSE
HoleToHoleClearance HoleToHoleClearance_Micro-Micro [AsMM(ViaDiameter) = 0.32 vs AsMM(ViaDiameter) = 0.32] p5: gap=11.81 allowstackedmicrovias=FALSE
HoleToHoleClearance HoleToHoleClearance_T-B_M1-M4 [InDrillLayerPair('Top Layer - Bottom Layer') vs InDrillLayerPair('Mid Layer 1 - Mid Layer 4')] p6 off: gap=17.72 allowstackedmicrovias=FALSE
HoleToHoleClearance HoleToHoleClearance_T-B_T-M1 [InDrillLayerPair('Top Layer - Bottom Layer') vs InDrillLayerPair('Top Layer - Mid Layer 1')] p7 off: gap=12.99 allowstackedmicrovias=FALSE
HoleToHoleClearance HoleToHoleClearance_T-B_M1-M2 [InDrillLayerPair('Top Layer - Bottom Layer') vs InDrillLayerPair('Mid Layer 1 - Mid Layer 2')] p8 off: gap=12.99 allowstackedmicrovias=FALSE
HoleToHoleClearance HoleToHoleClearance_T-B_M3-M4 [InDrillLayerPair('Top Layer - Bottom Layer') vs InDrillLayerPair('Mid Layer 3 - Mid Layer 4')] p9 off: gap=12.99 allowstackedmicrovias=FALSE
HoleToHoleClearance HoleToHoleClearance_T-B_M4-B [InDrillLayerPair('Top Layer - Bottom Layer') vs InDrillLayerPair('Mid Layer 4 - Bottom Layer')] p10 off: gap=12.99 allowstackedmicrovias=FALSE
HoleToHoleClearance HoleToHoleClearance_M1-M4_M1-M4 [InDrillLayerPair('Mid Layer 1 - Mid Layer 4') vs InDrillLayerPair('Mid Layer 1 - Mid Layer 4')] p11 off: gap=17.72 allowstackedmicrovias=FALSE
HoleToHoleClearance HoleToHoleClearance_M1-M4_T-M1-Shield [InDrillLayerPair('Mid Layer 1 - Mid Layer 4') and IsShieldingVia vs InDrillLayerPair('Top Layer - Mid Layer 1')] p12 off: gap=0 allowstackedmicrovias=TRUE
HoleToHoleClearance HoleToHoleClearance_T-M1-M1-M2-Shield [InDrillLayerPair('Top Layer - Mid Layer 1') and IsShieldingVia vs InDrillLayerPair('Mid Layer 1 - Mid Layer 2')] p13 off: gap=0 allowstackedmicrovias=TRUE
HoleToHoleClearance "HoleToHoleClearance_M1-M4_T-M1-Shield Manual" [InDrillLayerPair('Mid Layer 1 - Mid Layer 4') and (InRegionRelative(1100,200,1310,600) or InRegionRelative(1187,1493,1212,1553)) vs InDrillLayerPair('Top Layer - Mid Layer 1')] p14 off: gap=0 allowstackedmicrovias=TRUE
HoleToHoleClearance HoleToHoleClearance_M1-M4_T-M1 [InDrillLayerPair('Mid Layer 1 - Mid Layer 4') vs InDrillLayerPair('Top Layer - Mid Layer 1')] p15 off: gap=14.76 allowstackedmicrovias=FALSE
HoleToHoleClearance HoleToHoleClearance_M1-M4_M1-M2 [InDrillLayerPair('Mid Layer 1 - Mid Layer 4') vs InDrillLayerPair('Mid Layer 1 - Mid Layer 2')] p16 off: gap=14.76 allowstackedmicrovias=FALSE
HoleToHoleClearance HoleToHoleClearance_M1-M4_M3-M4 [InDrillLayerPair('Mid Layer 1 - Mid Layer 4') vs InDrillLayerPair('Mid Layer 3 - Mid Layer 4')] p17 off: gap=14.76 allowstackedmicrovias=FALSE
HoleToHoleClearance HoleToHoleClearance_M1-M4_M4-B [InDrillLayerPair('Mid Layer 1 - Mid Layer 4') vs InDrillLayerPair('Mid Layer 4 - Bottom Layer')] p18 off: gap=14.76 allowstackedmicrovias=FALSE
HoleToHoleClearance HoleToHoleClearance_T-M1_T-M1 [InDrillLayerPair('Top Layer - Mid Layer 1') vs InDrillLayerPair('Top Layer - Mid Layer 1')] p19 off: gap=11.81 allowstackedmicrovias=FALSE
HoleToHoleClearance HoleToHoleClearance_T-M1_M1-M2 [InDrillLayerPair('Top Layer - Mid Layer 1') vs InDrillLayerPair('Mid Layer 1 - Mid Layer 2')] p20 off: gap=11.81 allowstackedmicrovias=FALSE
HoleToHoleClearance HoleToHoleClearance_M1-M2_M1-M2 [InDrillLayerPair('Mid Layer 1 - Mid Layer 2') vs InDrillLayerPair('Mid Layer 1 - Mid Layer 2')] p21 off: gap=12.8 allowstackedmicrovias=FALSE
HoleToHoleClearance HoleToHoleClearance_M3-M4_M3-M4 [InDrillLayerPair('Mid Layer 3 - Mid Layer 4') vs InDrillLayerPair('Mid Layer 3 - Mid Layer 4')] p22 off: gap=12.8 allowstackedmicrovias=TRUE
HoleToHoleClearance HoleToHoleClearance_M3-M4_M4-B [InDrillLayerPair('Mid Layer 3 - Mid Layer 4') vs InDrillLayerPair('Mid Layer 4 - Bottom Layer')] p23 off: gap=11.81 allowstackedmicrovias=TRUE
HoleToHoleClearance HoleToHoleClearance_M4-B_M4-B_nRF53 [WithinRoom('nRF53') and InDrillLayerPair('Mid Layer 4 - Bottom Layer') vs WithinRoom('nRF53') and InDrillLayerPair('Mid Layer 4 - Bottom Layer')] p24 off: gap=8.66 allowstackedmicrovias=FALSE
HoleToHoleClearance HoleToHoleClearance_M4-B_M4-B [InDrillLayerPair('Mid Layer 4 - Bottom Layer') vs InDrillLayerPair('Mid Layer 4 - Bottom Layer')] p25 off: gap=12.8 allowstackedmicrovias=FALSE
MinimumAnnularRing [All] p1 off: minimumring=6
MinimumSolderMaskSliver MinimumSolderMaskSliver_exception [HasFootprint('SOTFL35P100X50-6N') or HasFootprint('DX07S016JA1R1500') or HasFootprint('DFN40P130X120X40-6N') or HasFootprint('BGA4C40P2X2_76X76X62') or HasFootprint('VM3011') or HasFootprint('WE-TPC_4848') or HasFootprint('BGA12C40P3X4_139X164X40') or HasFootprint('X2-DFN40P120X120X40_HS-7L')] p1: minsoldermaskwidth=1.97
MinimumSolderMaskSliver MinimumSolderMaskSliver_exception_1 [HasFootprint('TSQFP50P1600X1600X160-100N') or HasFootprint('BGA12C40P3X4_139X164X40')] p2: minsoldermaskwidth=2.36
MinimumSolderMaskSliver [All] p3: minsoldermaskwidth=2.93
NetAntennae NetAntennae_allowed [InNet('ANT') or InNet('PVSS1') or InNet('PVSS2')] p1: netantennaetolerance=1574.8
NetAntennae [All] p2: netantennaetolerance=0
PolygonConnect PolygonConnect_1 [isVia or HasFootprint('COAXIAL-SWF') or HasFootprint('2 PIN STARPOINT') or HasFootprint('C1608X06L-C1005X04M') or HasFootprint('UFDFN50P120X250X55-8N') or InNet('Shield')] p1: connectstyle=Direct reliefconductorwidth=10 reliefentries=4 polygonreliefangle="90 Angle" airgapwidth=10
PolygonConnect [All] p2: connectstyle=Relief reliefconductorwidth=10 reliefentries=4 polygonreliefangle="90 Angle" airgapwidth=7.87
RoomDefinition nPM6001 [InComponentClass('nPM6001')] p1 off: confinementstyle=ConfineIn formatcopy=TRUE lockcomponents=FALSE outline 544.19,1263.81 717.97,1263.81 717.97,1379.68 544.19,1379.68
RoomDefinition nRF53 [InComponentClass('nRF53')] p2 off: confinementstyle=ConfineIn formatcopy=TRUE lockcomponents=FALSE outline 557,859 842,859 842,1071.48 557,1071.48
RoutingVias "Schematic Routing Via Style_1" [InComponent('H2')] p1: holewidth=0 width=0 viastyle="Through Hole" minholewidth=0 minwidth=0 maxholewidth=78.74 maxwidth=78.74
RoutingVias "Schematic Routing Via Style" [InComponent('H1')] p2: holewidth=0 width=0 viastyle="Through Hole" minholewidth=0 minwidth=0 maxholewidth=78.74 maxwidth=78.74
RoutingVias RoutingVias_Buried_Laser [InDrillLayerPair('Mid Layer 1 - Mid Layer 2') or InDrillLayerPair('Mid Layer 3 - Mid Layer 4')] p3: holewidth=3.94 width=12.8 viastyle="Through Hole" minholewidth=3.94 minwidth=12.8 maxholewidth=3.94 maxwidth=12.8 useviatemplates=TRUE viatemplateguid#1={9ABB6B76-5394-44E6-A882-B3597929173E} viatemplatename#1=v32h10m0mx0
RoutingVias RoutingVias_Buried_Mech [InDrillLayerPair('Mid Layer 1 - Mid Layer 4')] p4: holewidth=9.84 width=19.68 viastyle="Through Hole" minholewidth=9.84 minwidth=19.68 maxholewidth=9.84 maxwidth=19.68 useviatemplates=TRUE viatemplateguid#1={8EF9FDDC-A461-4832-97D7-10F555954D9C} viatemplatename#1=v50h25
RoutingVias RoutingVias_TH [InDrillLayerPair('Top Layer - Bottom Layer')] p5: holewidth=9.84 width=19.68 viastyle="Through Hole" minholewidth=9.84 minwidth=19.68 maxholewidth=9.84 maxwidth=19.68 useviatemplates=TRUE viatemplateguid#1={8EF9FDDC-A461-4832-97D7-10F555954D9C} viatemplatename#1=v50h25
RoutingVias RoutingVias_Blind_Laser [InDrillLayerPair('Top Layer - Mid Layer 1') or InDrillLayerPair('Mid Layer 4 - Bottom Layer')] p6: holewidth=3.94 width=12.8 viastyle="Through Hole" minholewidth=3.94 minwidth=9.84 maxholewidth=3.94 maxwidth=12.8 useviatemplates=TRUE viatemplateguid#1={1F3E73C2-C6A8-4428-A676-A14C7D9AFDCB} viatemplateguid#2={9ABB6B76-5394-44E6-A882-B3597929173E} viatemplatename#1=v25h10m0mx0 viatemplatename#2=v32h10m0mx0
ShortCircuit ShortCircuit_PVSS [InNet('PVSS1') or InNet('PVSS2') vs InNet('GND')] p1: allowed=TRUE
ShortCircuit [All] p2: allowed=FALSE
SilkToSolderMaskClearance SilkscreenOverComponentPads [IsPad] p1: minsilkscreentomaskgap=10 clearancetoexposedcopper=TRUE
SolderMaskExpansion SolderMaskExpansion_1 [IsVia] p1: expansion=4 istentingtop=TRUE useseparateexpansions=TRUE expansionbottom=4 istentingbottom=TRUE
SolderMaskExpansion SolderMaskExpansion_2 [HasFootprint('BGAS61C20P11X11_270X412X52') or HasFootprint('AQFN40P700X700X85_HS-99N') or HasFootprint('BGA32C40P6X6_238X238X56') or HasFootprint('QFN40P600X600X90-48N') or HasFootprint('SON40P100X60-8N') or HasFootprint('DFN40P130X120X40-6N') or HasFootprint('CL-2025') or HasFootprint('VM3011') or HasFootprint('WE-TPC_4848')or HasFootprint('XQFN40P180X260X50-16N') or HasFootprint('BGA4C40P2X2_76X76X62') or HasFootprint('CL-2025') or HasFootprint('BGA25C40P5X5_200X200X50')] p2: expansion=1.97 istentingtop=FALSE
SolderMaskExpansion SolderMaskExpansion_3 [HasFootprint('TSQFP50P1600X1600X160-100N') or HasFootprint('BGA12C40P3X4_139X164X40') or HasFootprint('Molex_502774-0891') or HasFootprint('LED_DUAL_0606') or HasFootprint('DFN65P100X40-3L')] p3: expansion=2.36 istentingtop=FALSE
SolderMaskExpansion [All] p4: expansion=2.95 istentingtop=FALSE
SupplyNets "Schematic Supply Nets_34" [InNet('Shield')] p1: voltage=0.000
SupplyNets "Schematic Supply Nets_33" [InNet('3V3_IND')] p2: voltage=0.000
SupplyNets "Schematic Supply Nets_8" [InNet('1V8_IND')] p3: voltage=0.000
SupplyNets "Schematic Supply Nets_30" [InNet('VDD_nRF91_RES')] p4: voltage=0.000
SupplyNets "Schematic Supply Nets_20" [InNet('VDD_RF_FE_3V3_SP')] p5: voltage=0.000
SupplyNets "Schematic Supply Nets_32" [InNet('VDD_SENS')] p6: voltage=0.000
SupplyNets "Schematic Supply Nets_31" [InNet('VDD_EXP_BRD')] p7: voltage=0.000
SupplyNets "Schematic Supply Nets_29" [InNet('VDD_RF_FE_3V3')] p8: voltage=0.000
SupplyNets "Schematic Supply Nets_28" [InNet('VBAT')] p9: voltage=0.000
SupplyNets "Schematic Supply Nets_27" [InNet('VDD_BMM350')] p10: voltage=0.000
SupplyNets "Schematic Supply Nets_26" [InNet('VDD_BMI270')] p11: voltage=0.000
SupplyNets "Schematic Supply Nets_25" [InNet('VDD_ENV')] p12: voltage=0.000
SupplyNets "Schematic Supply Nets_24" [InNet('PWRIOVDD')] p13: voltage=0.000
SupplyNets "Schematic Supply Nets_23" [InNet('1V8_SW')] p14: voltage=0.000
SupplyNets "Schematic Supply Nets_22" [InNet('1V8')] p15: voltage=0.000
SupplyNets "Schematic Supply Nets_21" [InNet('VDD_ACC')] p16: voltage=0.000
SupplyNets "Schematic Supply Nets_19" [InNet('3V3')] p17: voltage=0.000
SupplyNets "Schematic Supply Nets_18" [InNet('GND')] p18: voltage=0.000
SupplyNets "Schematic Supply Nets_17" [InNet('VDD_nRF53')] p19: voltage=0.000
SupplyNets "Schematic Supply Nets_16" [InNet('VSYS_SW')] p20: voltage=0.000
SupplyNets "Schematic Supply Nets_15" [InNet('PVSS2')] p21: voltage=0.000
SupplyNets "Schematic Supply Nets_14" [InNet('PVSS1')] p22: voltage=0.000
SupplyNets "Schematic Supply Nets_13" [InNet('VBUS')] p23: voltage=0.000
SupplyNets "Schematic Supply Nets_12" [InNet('VDDIO_nRF70')] p24: voltage=0.000
SupplyNets "Schematic Supply Nets_11" [InNet('VOUT_BUCK0')] p25: voltage=0.000
SupplyNets "Schematic Supply Nets_10" [InNet('VDD_BUCK')] p26: voltage=0.000
SupplyNets "Schematic Supply Nets_9" [InNet('VBUS_CONN')] p27: voltage=0.000
SupplyNets "Schematic Supply Nets_7" [InNet('VOUT_BUCK3')] p28: voltage=0.000
SupplyNets "Schematic Supply Nets_6" [InNet('VBUSOUT')] p29: voltage=0.000
SupplyNets "Schematic Supply Nets_5" [InNet('VBAT_nRF70')] p30: voltage=0.000
SupplyNets "Schematic Supply Nets_4" [InNet('VDD_LED')] p31: voltage=0.000
SupplyNets "Schematic Supply Nets_3" [InNet('VDD_nRF91')] p32: voltage=0.000
SupplyNets "Schematic Supply Nets_2" [InNet('VDD_RF_FE_SR')] p33: voltage=0.000
SupplyNets "Schematic Supply Nets_1" [InNet('VSYS')] p34: voltage=0.000
SupplyNets "Schematic Supply Nets" [InNet('VDD_MEM')] p35: voltage=0.000
UnpouredPolygon [All] p1 off:
Width "Width_nRF5340 and nPM6001" [OnLayer('Bottom Layer') and WithinRoom('nRF53') or OnLayer('Mid Layer 4') and WithinRoom('nPM6001')] p1: maxlimit=10 minlimit=4.13 preferedwidth=10
Width Width_Diff [(InDifferentialPairClass('All Differential Pairs'))] p2: maxlimit=6.5 minlimit=5.91 preferedwidth=6.5
Width Width_RF [InNetClass('RF')] p3: maxlimit=25.12 minlimit=1.39 preferedwidth=2.43 toplayer_minwidth=25.12 toplayer_prefwidth=25.12 midlayer1_maxwidth=1.39 midlayer1_prefwidth=1.39 midlayer2_minwidth=2.43 midlayer2_maxwidth=2.43 midlayer3_minwidth=2.43 midlayer3_maxwidth=2.43 midlayer4_maxwidth=1.39 midlayer4_prefwidth=1.39 bottomlayer_minwidth=25.12 bottomlayer_prefwidth=25.12 impedanceprofiledriven=TRUE impedanceprofileid={C8E51A2C-D176-4063-A735-4B14FCDA7D28} impedanceprofilevalue=50.000000 minimp=50.000000 maximp=50.000000 favimp=50.000000 checkconnectedcopper=TRUE
Width Width_RF_BLE/WIFI [InNetClass('RF_BLE/WIFI')] p4: maxlimit=11.42 minlimit=1.39 preferedwidth=2.43 toplayer_minwidth=11.42 toplayer_prefwidth=11.42 midlayer1_maxwidth=1.39 midlayer1_prefwidth=1.39 midlayer2_minwidth=2.43 midlayer2_maxwidth=2.43 midlayer3_minwidth=2.43 midlayer3_maxwidth=2.43 midlayer4_maxwidth=1.39 midlayer4_prefwidth=1.39 bottomlayer_minwidth=11.42 bottomlayer_prefwidth=11.42 impedanceprofiledriven=TRUE impedanceprofileid={BFD42E9A-6BB2-400D-A7A0-5B5FD1E38EF8} impedanceprofilevalue=50.000000 minimp=50.000000 maximp=50.000000 favimp=50.000000 checkconnectedcopper=TRUE
Width [All] p5: maxlimit=118.11 minlimit=4.92 preferedwidth=4.92
18 further rules are at their usual default settings.

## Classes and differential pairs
pad class NPTH: H1- H2-
component class nRF53: U6
component class nPM6001: U25
component class pca20065_nrf9151: C1 C2 C3 C4 C5 C6 C10 C31 C32 C33 C35 C36 C103 FB1 L5 M1 Q13 Q14 R1 R2 R54 R106 R107 R108 SB6 TP22 TP23 TP24 TP32 TP33 U9
component class pca20065_nrf5340: C12 C13 C15 C16 C17 C18 C19 C20 C21 C22 C23 C24 C25 C26 C27 C28 C29 CR1 F1 L1 L2 L3 L4 R4 R6 R10 R11 R16 SB7 TP5 U6 X1 X2
net class POWER: 1V8_SW NetU25_C5 NetU25_D1 VOUT_BUCK0 VOUT_BUCK3 VSYS_SW
net class RF_BLE/WIFI: ANT NetC24_2 NetC25_2 NetCR1_2 NetF2_1 NetF2_3 NetF2_6 NetU21_9
net class RF: GPS_RF1 GPS_RF2 NetA1_1 NetJ1_1 NetJ1_3 NetU9_5 NetZ1_2 NetZ5_1 NetZ21_1 RF1 RF2 RF3 RF4 RFC
differential pair D:J6: +D:J6_P -D:J6_N
differential pair USB.D: +USB.D_P -USB.D_N

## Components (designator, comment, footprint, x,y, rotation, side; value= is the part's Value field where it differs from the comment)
A1 "NN03-310" NN03-310_RF_ALT1 2011.81,669.29 r270 top locked
A2 "NN03-320" NN03-320 2011.81,1594.49 r90 top
A3 "NN02-101" NN02-101_Corner 1043.31,2017.72 r90 top
C1 "15pF" CAPC0603X03L_C 984.59,344.4 r270 top
C2 "100nF" CAPC0603X03L_C 1007.22,344.4 r270 top
C3 "47µF" CAPC2012X11L 1063.24,417.93 r90 top
C4 "100nF" CAPC0603X03L_C 556.79,715.16 r270 top
C5 "4.7µF" CAPC1005X04L 530.62,706.69 r270 top
C6 "4.7µF" CAPC2012X11L 1063.24,535.47 r90 top
C7 "100nF" CAPC0603X03L_C 637.25,464.61 r90 bottom
C8 "2.2µF" CAPC1005X04L_C2 642.74,1035.47 r0 top
C9 "1.0nF" CAPC0603X03L_C 571.25,1762.86 r180 bottom
C10 "100nF" CAPC0603X03L_C 704.55,336.72 r270 top
C11 "100nF" CAPC0603X03L_C 321.85,1153.54 r270 bottom
C12 "100nF" CAPC0603X03L_C 817.9,964.76 r0 bottom
C13 "100nF" CAPC0603X03L_C 794.64,848.62 r270 bottom
C14 "1.0µF" CAPC1005X04L 326.77,1092.52 r90 bottom
C15 "1.0µF" CAPC1005X04L 686.01,812.2 r270 bottom
C16 "1.0µF" CAPC1005X04L 628.92,1177.36 r180 bottom
C17 "1.0µF" CAPC1005X04L 740.14,1145.87 r90 bottom
C18 "2.2nF" CAPC0603X03L_C 800.18,1032.68 r0 bottom
C19 "100nF" CAPC0603X03L_C 545.26,851.57 r180 bottom
C20 "100nF" CAPC0603X03L_C 545.26,897.84 r180 bottom
C21 "100nF" CAPC0603X03L_C 770.65,1088.78 r90 bottom
C22 "1.0µF" CAPC1005X04L 531.48,1136.02 r270 bottom
C23 "1.0µF" CAPC1005X04L 637.78,1121.26 r90 bottom
C24 "0.7pF" CAPC0603X03L_C 829.71,999.21 r270 bottom
C25 "N.C." CAPC0603X03L_C_NC 896.64,999.21 r270 bottom
C26 "4.7µF" CAPC1608X06L 490.14,1125.2 r90 bottom
C27 "4.7µF" CAPC1608X06L 524.1,1014.47 r180 bottom
C28 "100nF" CAPC0603X03L_C 730.3,1076.97 r180 bottom
C29 "1.0µF" CAPC1005X04L 606.28,1121.26 r90 bottom
C30 "2.2µF" CAPC1608X06L 1144.68,1508.86 r90 top
C31 "39pF" CAPC0603X03L_C 1232.28,1503.94 r270 top
C32 "100pF" CAPC0603X03L_C 1350.39,1600.39 r270 top
C33 "100nF" CAPC0603X03L_C 1350.39,1557.58 r90 top
C34 "100nF" CAPC0603X03L_C 1120.08,229.33 r90 top
C35 "100nF" CAPC0603X03L_C 1326.77,1507.87 r90 bottom
C36 "100pF" CAPC0603X03L_C 1350.39,1507.87 r90 bottom
C37 "100nF" CAPC0603X03L_C 1035.43,710.63 r270 bottom
C38 "100pF" CAPC0603X03L_C 1390.57,188.96 r90 bottom
C39 "100nF" CAPC0603X03L_C 850.6,1057.92 r0 top
C40 "100nF" CAPC0603X03L_C 783.46,1381.89 r270 bottom
C41 "100nF" CAPC0603X03L_C 1081.42,1569.89 r270 top
C42 "2.2µF" CAPC1005X04L 1073.82,1209.65 r90 top
C43 "10nF" CAPC0603X03L_C 286.42,1486.22 r270 bottom
C44 "100nF" CAPC0603X03L_C 186.02,1486.22 r90 bottom
C45 "1.0µF" CAPC1005X04L 1040.35,1209.64 r270 top
C46 "1.0µF" CAPC1608X06L 229.58,1669.4 r0 bottom
C47 "10µF" CAPC1608X06L 599.41,1698.82 r270 bottom
C48 "10µF" CAPC1608X06L 599.41,1596.46 r90 bottom
C49 "10µF" CAPC1608X06L 229.58,1626.19 r0 bottom
C50 "1.0µF" CAPC1608X06L 229.58,1712.6 r0 bottom
C51 "2.2µF" CAPC1608X06L 229.58,1562.99 r0 bottom
C52 "10µF" CAPC1608X06L 572.83,1791.5 r180 bottom
C53 "10µF" CAPC1608X06L 676.18,1523.62 r0 bottom
C54 "10nF" CAPC0603X03L_C 1052.16,320.87 r180 top
C55 "100nF" CAPC0603X03L_C 629.92,276.97 r90 bottom
C56 "100nF" CAPC0603X03L_C 1581.65,1929.58 r0 bottom
C57 "100nF" CAPC0603X03L_C 1518.7,1929.58 r0 bottom
C58 "1.0nF" CAPC0603X03L_C 224.56,1594.38 r0 bottom
C59 "N.C." CAPC0603X03L_C_NC 984.25,47.24 r90 top
C60 "0.47µF" CAPC0603X03L_C 1012.8,1226.38 r90 top
C61 "0.47µF" CAPC0603X03L_C 885.63,1581.7 r270 top
C62 "100nF" CAPC0603X03L_C 863.19,1581.7 r90 top
C63 "4.7µF" CAPC1608X06L 802.68,1572.44 r0 top
C64 "4.7µF" CAPC1608X06L 775.94,1264.65 r90 top
C65 "4.7µF" CAPC1608X06L 775.94,1170.17 r270 top
C66 "10nF" CAPC0603X03L_C 939.32,1257.76 r180 top
C67 "2.2µF" CAPC1608X06L 956.06,1221.35 r180 top
C68 "4.7µF" CAPC1608X06L 775.39,1526.57 r0 top
C69 "22nF" CAPC0603X03L_C 802.95,1492.55 r0 top
C70 "0.22µF" CAPC0603X03L_C 802.95,1469.99 r0 top
C71 "2.2µF" CAPC0603X03L_C 802.95,1447.43 r0 top
C72 "1.0µF" CAPC1005X04L 773.42,1398.58 r0 top
C73 "1.0µF" CAPC1005X04L 773.42,1366.14 r0 top
C74 "1.0nF" CAPC0603X03L_C 574.53,1550.89 r180 bottom
C75 "100nF" CAPC0603X03L_C 117.13,591.54 r270 bottom
C76 "100nF" CAPC0603X03L_C 32.48,591.54 r90 bottom
C77 "10µF" CAPC1608X06L 521.65,1371.06 r90 bottom
C78 "10µF" CAPC1608X06L 449.8,1344.49 r180 bottom
C79 "100nF" CAPC0603X03L_C 437.01,1489.17 r270 bottom
C80 "10µF" CAPC1608X06L 521.65,1272.64 r270 bottom
C81 "4.7µF" CAPC1608X06L 449.8,1299.21 r180 bottom
C82 "1.0µF" CAPC0603X03L_C 612.66,1393.52 r0 bottom
C83 "1.0µF" CAPC0603X03L_C 608.72,1226.19 r0 bottom
C84 "1.0µF" CAPC0603X03L_C 609.25,1249.02 r0 bottom
C85 "1.0µF" CAPC0603X03L_C 701.24,1394.5 r0 bottom
C86 "100nF" CAPC0603X03L_C 783.46,1340.55 r90 bottom
C87 "100nF" CAPC0603X03L_C 847.44,1438.98 r0 bottom
C88 "100nF" CAPC0603X03L_C 783.46,1423.23 r90 bottom
C89 "10µF" CAPC1608X06L 726.38,1451.77 r90 bottom
C90 "10µF" CAPC1608X06L 843.5,1703.74 r270 bottom
C91 "100nF" CAPC0603X03L_C 892.87,954.47 r90 top
C92 "100nF" CAPC0603X03L_C 706.7,1004.57 r270 top
C93 "100nF" CAPC0603X03L_C 616.14,988.83 r270 top
C94 "10µF" CAPC1608X06L 535.67,1871.06 r180 top
C95 "10µF" CAPC1608X06L 455.26,1955.35 r90 top
C96 "10µF" CAPC1608X06L 782.58,1580.39 r270 bottom
C97 "10µF" CAPC1608X06L 942.96,1580.39 r270 bottom
C98 "10µF" CAPC1608X06L 201.8,1835.31 r270 bottom
C99 "10pF" CAPC0603X03L_C 427.43,1026.38 r0 bottom
C100 "10pF" CAPC0603X03L_C 383.25,1026.38 r180 bottom
C101 "10pF" CAPC0603X03L_C 107.57,1469.06 r270 bottom
C102 "10pF" CAPC0603X03L_C 81.46,1469.06 r270 bottom
C103 "10µF" CAPC1608X06L 798.19,355.94 r0 top
CR1 "EZA-EG1N50AC" RESC0603X03L_C 956.34,1089.61 r0 bottom
D3 "TPD3F303DPVR" SON50P210X160X65_HS-9N 1039.37,133.86 r90 top
F1 "SAFFB2G45MA0F0A" SAFFB2G45MA0F0A 956.69,1041.36 r90 bottom
F2 "LFD_Diplexer" CAF-50P160X80-6N 785.43,1712.6 r90 top value=LFD182G45DCJD247
FB1 "120R/0.7A" INDC1608X06L 892,355.94 r180 top
FB2 "120R/0.55A" INDC1005X04L 236.22,1477.36 r180 bottom
FB3 "BLM21AG102SN1D" INDC2012X11L 509.1,1951.41 r90 top
FB4 "BLM21AG102SN1D" INDC2012X11L 863.48,1553.81 r0 bottom
FB5 "BLM21AG102SN1D" INDC2012X11L 257.76,1845.37 r270 bottom
Fid1 "Fiducial mark" Fiducial_Round-Square 255.91,98.43 r180 top value=N.A.
Fid2 "Fiducial mark" Fiducial_Round-Square 2007.87,2007.87 r0 top value=N.A.
H1 "MountingHole_NPTH" MountingHole_3.2_M3 127.95,127.95 r180 top value=MountingHole_3.2_M3
H2 "MountingHole_NPTH" MountingHole_3.2_M3 1811.02,1958.66 r180 top locked value=MountingHole_3.2_M3
J1 "MM8130-2600" COAXIAL-SWF 1212.6,488.19 r0 top
J2 "MM8130-2600" COAXIAL-SWF 778.25,1874.93 r270 top
J3 "HDR-3, 1mm" SM03B-SRSS-TB 334.65,1921.26 r270 bottom locked
J4 "SF72S006VBxR2500" SF72S006VBxR2500 812.01,35.43 r180 bottom locked value=SF72S006VBDR2500
J6 "USB-C 2.0" USB4110 227.56,1198.82 r90 bottom locked
L1 "10µH" INDC1608X06L 702.74,1133.07 r270 bottom
L2 "10µH" INDC1608X06L 568.88,1120.28 r270 bottom
L3 "2.2nH" INDC0603X03L_C 796.24,987.4 r180 bottom
L4 "2.2nH" INDC0603X03L_C 863.17,987.4 r180 bottom
L5 "9.1nH" INDC1005X04L_WW 1196.85,1600.39 r90 top
L6 "3.3µH" INDC2520X10N 849.41,1189.43 r270 top
L7 "2.2µH" INDC2016X10N 673.23,1717.52 r270 bottom
L8 "2.2µH" INDC2016X10N 692.91,1597.44 r180 bottom
L9 "2.2µH" INDC2016X10N 432.09,1414.37 r180 bottom
L10 "470nH" INDC1608X06L 449.8,1253.94 r180 bottom
LABEL1 "12x38mm" LabelSilk_12x38 1373.03,1709.23 r270 top
LED1 "LED RGB" LED_RGB_0606 1968.5,1889.76 r0 top locked
LED2 "LED RGB" OVSRRGBCC3_Side 78.74,805.12 r0 top
LED3 "LED RGB" OVSRRGBCC3_Side 78.74,1198.82 r0 top
LOGO1 "WEE Symbol" WEE_3x4.5mm 1324.97,2001.86 r0 top
M1 "nRF9151" "LGA50P1210X1110X130-113N - 98A0113SP002-O01" 797.93,618.11 r0 top value=nRF9151-LACAADA
NT1 "Net tie" "2 PIN STARPOINT" 574.93,1730.31 r180 bottom net-tie
NT2 "Net tie" "2 PIN STARPOINT" 620.94,1531.5 r180 bottom net-tie
P1 "SM04B-SRSS-TB" SM04B-SRSS-TB 47.24,805.12 r90 bottom locked
P8 "Pin Header 2x5" HDR_2x5-SMD-1.27mm-ANG 263.78,381.89 r270 top locked
P9 "Card Edge, 0.8mm" 10056847-101LF 324.8,381.89 r90 bottom locked
Q1 "RV2C010UNT2L" DFN65P100X40-3L 352.36,860.24 r90 bottom
Q2 "DMN2990UDJ" SOTFL35P100X50-6N 416.78,909.81 r270 bottom
Q3 "RV2C010UNT2L" DFN65P100X40-3L 1934.06,1942.91 r180 bottom
Q4 "DMN2990UDJ" SOTFL35P100X50-6N 1889.76,1870.08 r90 bottom
Q5 "RV2C010UNT2L" DFN65P100X40-3L 754.92,1674.21 r90 bottom
Q6 "DMC2990UDJ" SOTFL35P100X50-6N 256.07,1935.22 r0 bottom
Q13 "DMC2990UDJ" SOTFL35P100X50-6N 748.03,418.31 r0 bottom
Q14 "RV2C010UNT2L" DFN65P100X40-3L 767.72,361.22 r270 bottom
R1 "10k" RESC0603X03L_C 796.94,427.19 r270 bottom
R2 "1k" RESC0603X03L_C 727.55,336.72 r90 top
R3 "1M0" RESC0603X03L_C 342.52,1377.95 r180 bottom
R4 "150R" RESC0603X03L_C 771.84,848.62 r270 bottom
R5 "0R" RESC0603X03L_C 72.97,582.18 r270 top
R6 "150R" RESC0603X03L_C 822.48,848.62 r270 bottom
R7 "47k" RESC0603X03L_C 332.68,1489.17 r270 bottom
R8 "330k" RESC0603X03L_C 356.3,1489.17 r270 bottom
R9 "1M0" RESC0603X03L_C 674.21,1417.32 r180 bottom
R10 "2R2" RESC0603X03L_C 501.95,1184.25 r0 bottom
R11 "0R" RESC0603X03L_C 727.38,828.74 r90 bottom
R12 "100R" RESC0603X03L_C 1938.98,1913.39 r0 bottom
R13 "39R" RESC0603X03L_C 1938.98,1889.76 r0 bottom
R14 "39R" RESC0603X03L_C 1938.98,1866.14 r0 bottom
R15 "4M7" RESC0603X03L_C 72.92,536.33 r270 top
R16 "150R" RESC0603X03L_C 844.97,848.62 r270 bottom
R17 "10k" RESC0603X03L_C 702.36,213.46 r180 bottom
R18 "100k" RESC0603X03L_C 657.68,213.46 r180 bottom
R19 "100R" RESC0603X03L_C 356.3,920.28 r180 bottom
R20 "39R" RESC0603X03L_C 356.3,897.64 r180 bottom
R21 "39R" RESC0603X03L_C 356.3,942.91 r180 bottom
R22 "4k7" RESC0603X03L_C 445.78,581.29 r90 top
R23 "4k7" RESC0603X03L_C 422.16,581.29 r90 top
R24 "0.1R" RESC1005X04L 448.82,632.87 r180 bottom
R25 "N.C." RESC0603X03L_C_NC 817.36,1618.05 r270 bottom
R26 "1k" RESC0603X03L_C 783.46,1465.55 r270 bottom
R27 "0R" RESC0603X03L_C 1086.61,652.56 r90 bottom
R28 "0R" RESC0603X03L_C 1075.79,685.04 r0 bottom
R29 "0R" RESC0603X03L_C 1086.61,717.52 r270 bottom
R30 "1M0" RESC0603X03L_C 304.16,1824.55 r90 bottom
R31 "0R" RESC0603X03L_C 416.21,1057.79 r90 bottom
R32 "0R" RESC0603X03L_C 745.75,213.46 r180 bottom
R33 "1M0" RESC0603X03L_C 905.94,1636.75 r90 bottom
R34 "0R" RESC0603X03L_C 394.47,1057.79 r90 bottom
R38 "1M0" RESC0603X03L_C 438.96,846.46 r270 bottom
R41 "1M0" RESC0603X03L_C 383.86,846.46 r270 bottom
R42 "1M0" RESC0603X03L_C 411.42,846.46 r270 bottom
R43 "100k" RESC0603X03L_C 1047.24,744.09 r0 bottom
R44 "1M0" RESC0603X03L_C 1929.13,1972.44 r0 bottom
R45 "1M0" RESC0603X03L_C 1849.41,1870.08 r270 bottom
R46 "1M0" RESC0603X03L_C 1896.65,1922.24 r270 bottom
R49 "1M0" RESC0603X03L_C 1052.17,343.5 r0 top
R50 "100k" RESC0603X03L_C 1035.43,667.32 r90 bottom
R53 "100k" RESC0603X03L_C 978.01,1288.71 r270 bottom
R54 "1M0" RESC0603X03L_C 1303.15,1507.87 r90 bottom
R56 "N.C." RESC0603X03L_C_NC 1144.68,1570.01 r180 bottom
R58 "100k" RESC0603X03L_C 1144.21,1403.54 r0 top
R59 "100k" RESC0603X03L_C 1144.21,1381.89 r0 top
R60 "100k" RESC0603X03L_C 1144.21,1447.83 r180 top
R61 "100k" RESC0603X03L_C 967.99,1187.3 r0 top
R62 "100k" RESC0603X03L_C 786.42,1674.21 r90 bottom
R64 "100k" RESC0603X03L_C 206.85,1932.27 r270 bottom
R106 "10k" RESC0603X03L_C 753.06,481.68 r0 bottom
R107 "100k" RESC0603X03L_C 753.06,458.82 r0 bottom
R108 "N.C." RESC0603X03L_C_NC 735.41,365.19 r270 bottom
SB1 "Solderbridge" Solderbridge 1302.66,514.76 r0 bottom
SB4 "Solderbridge" Solderbridge_Shorted 912.32,1061.94 r270 top net-tie
SB5 "Solderbridge" Solderbridge_Shorted 1407.49,1910.93 r0 bottom net-tie
SB6 "Solderbridge" Solderbridge_Shorted 726.12,293.4 r180 top net-tie
SB7 "Solderbridge" Solderbridge_Shorted 258.09,1831.91 r90 top net-tie
SB8 "Solderbridge" Solderbridge_Shorted 241.91,617.57 r0 top net-tie
SB9 "Solderbridge" Solderbridge_Shorted 241.91,664.23 r0 top net-tie
SB10 "Solderbridge" Solderbridge_Shorted 741.78,1007.02 r270 top net-tie
SBI2 "Solderbridge" Solderbridge 1302.66,455.71 r180 bottom
ST1 "Net tie" "2 PIN STARPOINT" 883.65,1082.91 r180 top net-tie
ST2 "Net tie" "2 PIN STARPOINT" 981.03,1560.17 r180 bottom net-tie
ST3 "Net tie" "2 PIN STARPOINT" 981.03,1544.07 r180 bottom net-tie
ST4 "Net tie" "2 PIN STARPOINT" 741.78,1048.69 r90 top net-tie
ST5 "Net tie" "2 PIN STARPOINT" 863.19,1687.36 r180 bottom net-tie
ST7 "Net tie" "2 PIN STARPOINT" 797.35,1484.77 r90 bottom net-tie
ST9 "Net tie" "2 PIN STARPOINT" 751.97,1459.65 r90 bottom net-tie
SW1 "Switch" Switch-Slide-RA-J-Lead-DPDT-8.5x3.5mm 92.52,1694.88 r90 bottom locked
SW2 "AYZ0102AGRLC" AYZ0102AGRLC 629.92,70.87 r180 bottom locked
SW3 "PB SW" L-KLS7-TS6616B-2.5-160-T 1094.49,1043.31 r0 top locked
SW4 "L-KLS7-TS5401A-1.35-250-T" L-KLS7-TS5401A-1.35-250-T 230.31,2027.56 r0 bottom
TP1 "Ø1.5mm,SMD" TP_SMD_D1.5mm 413.39,255.91 r0 top
TP2 "Ø1.5mm,SMD" TP_SMD_D1.5mm 255.91,981.39 r270 top
TP3 "Ø1.5mm,SMD" TP_SMD_D1.5mm 137.8,981.39 r270 top
TP4 "Ø1.5mm,SMD" TP_SMD_D1.5mm 275.59,1929.13 r180 top
TP5 "Ø1.5mm,SMD" TP_SMD_D1.5mm 509.68,456.22 r180 top
TP7 "Ø0.7mm,SMD" TP_SMD_D0.7mm 773.35,883.61 r90 top
TP8 "Ø1.0mm,SMD" TP_SMD_D1.0mm 1145.87,1661.19 r180 top
TP9 "Ø1.5mm,SMD" TP_SMD_D1.5mm 340.26,863.28 r270 top
TP10 "Ø1.5mm,SMD" TP_SMD_D1.5mm 340.26,745.17 r270 top
TP11 "Ø1.0mm,SMD" TP_SMD_D1.0mm 788.39,1724.41 r0 bottom
TP12 "Ø1.5mm,SMD" TP_SMD_D1.5mm 374.02,1257.87 r0 top
TP13 "Ø1.5mm,SMD" TP_SMD_D1.5mm 492.13,1139.76 r0 top
TP14 "Ø1.5mm,SMD" TP_SMD_D1.5mm 374.02,981.39 r0 top
TP15 "Ø1.5mm,SMD" TP_SMD_D1.5mm 374.02,1139.76 r180 top
TP16 "Ø1.5mm,SMD" TP_SMD_D1.5mm 1141.73,137.8 r0 top
TP17 "Ø1.5mm,SMD" TP_SMD_D1.5mm 222.15,863.28 r90 top
TP18 "Ø1.5mm,SMD" TP_SMD_D1.5mm 492.13,981.39 r90 top
TP19 "Ø1.5mm,SMD" TP_SMD_D1.5mm 222.15,745.17 r90 top
TP20 "Ø0.7mm,SMD" TP_SMD_D0.7mm 891.46,883.61 r90 top
TP21 "Ø1.0mm,SMD" TP_SMD_D1.0mm 1320.47,858.07 r180 bottom
TP22 "Ø1.0mm,SMD" TP_SMD_D1.0mm 1159.79,1317.77 r180 top
TP23 "Ø1.0mm,SMD" TP_SMD_D1.0mm 637.8,704.72 r0 bottom
TP24 "Ø1.0mm,SMD" TP_SMD_D1.0mm 1266.62,1204.56 r180 top
TP25 "Ø1.0mm,SMD" TP_SMD_D1.0mm 1320.47,1008.07 r180 bottom
TP26 "Ø1.0mm,SMD" TP_SMD_D1.0mm 1120.47,858.07 r180 bottom
TP27 "Ø1.5mm,SMD" TP_SMD_D1.5mm 531.5,255.91 r180 top
TP28 "Ø1.5mm,SMD" TP_SMD_D1.5mm 649.61,137.8 r180 top
TP29 "Ø1.5mm,SMD" TP_SMD_D1.5mm 649.61,255.91 r180 top
TP30 "Ø1.5mm,SMD" TP_SMD_D1.5mm 255.91,1257.87 r0 top
TP31 "Ø1.5mm,SMD" TP_SMD_D1.5mm 255.91,1139.76 r0 top
TP32 "Ø1.5mm,SMD" TP_SMD_D1.5mm 413.39,137.8 r180 top
TP33 "Ø1.5mm,SMD" TP_SMD_D1.5mm 531.5,137.8 r180 top
TP34 "Ø1.0mm,SMD" TP_SMD_D1.0mm 1020.47,858.07 r180 bottom
TP35 "Ø1.5mm,SMD" TP_SMD_D1.5mm 146.68,1929.13 r0 top
TP36 "Ø1.5mm,SMD" TP_SMD_D1.5mm 1209.44,784.45 r0 top
U1 "NLAS5223BMNR2G" UFQFN40P140X180X55-10N 645.12,390.01 r270 bottom
U2 "TCK106AG" BGA4C40P2X2_76X76X62 372.05,1338.58 r0 bottom
U3 "TCK106AG" BGA4C40P2X2_76X76X62 486.22,848.43 r0 bottom
U4 "TCK106AG" BGA4C40P2X2_76X76X62 574.8,500 r270 bottom
U5 "TCK108AG" BGA4C40P2X2_76X76X62 856.73,1618.05 r270 bottom
U6 "nRF5340-CLAAD0" BGA95C35P12X11_437X397X50 675.18,959.84 r180 bottom
U7 "GD25LE255ELIG" BGA32C50P6X8_350X400X50 922.24,689.96 r90 bottom
U8 "ECMF02-4CMX8" UFDFN50P120X250X55-8N 404.6,1115.09 r270 bottom
U9 "SKY65943-11" SKY65943-11 1279.53,1590.55 r180 top
U10 "TCK106AG" BGA4C40P2X2_76X76X62 1145.2,1583.27 r180 top
U11 "nPM1300-QEAAD0" Nordic_QFN50P500X500X90-33N 425.2,1637.8 r180 bottom
U12 "FSA2466UMX" XQFN40P180X260X50-16N 706.69,274.61 r270 bottom
U13 "TCK106AG" BGA4C40P2X2_76X76X62 1144.68,1528.67 r180 bottom
U14 "TCK106AG" BGA4C40P2X2_76X76X62 130.68,585.22 r0 top
U15 "MFFx_M2M_UICC" SON127P600X90_HS-8N 862.2,192.91 r270 top locked value="M2M UICC"
U16 "NX3DV2567" XQFN40P180X260X50-16N 1039.37,249.02 r270 top
U17 "QM13345" PQFN40P110X150X50-10N 1288.12,216.52 r90 top
U18 "BMI270" BMI270 832.41,985.38 r90 top
U20 "ADXL367" LGA50P220X230X97-12N 849.41,1371.06 r180 bottom
U21 "nRF7002-QFAAB0" QFN40P600X600X60-48N 974.41,1408.46 r270 top value=nRF7002-QFAA
U22 "BGS12xN6" TSNP-6-8 765.75,1631.89 r90 top value=BGS12WN6E6327XTSA1
U23 "BME688" BME680 1545.28,2008.32 r90 bottom
U24 "TXS0102YZPR" BGA8C50P2X4_89X189X50 74.8,591.54 r180 bottom
U25 "nPM6001-CAAAF0" BGA45C40P5X9_217X364X49 632.87,1321.85 r90 bottom locked
U26 "BMM350" BGA9C40P3X3_128X128X54 660.95,977.61 r180 top
X1 "32MHz" BT-XTAL_2016 849.6,1104.73 r90 bottom
X2 "32.768kHz" XTAL_2012 514.55,956.3 r180 bottom
X3 "40MHz" BT-XTAL_1612 727.17,1464.57 r90 top
Z1 "6.0pF" C1608X06L-C1005X04M#1 1307.83,320.55 r90 top
Z2 "0R" C1608X06L-C1005X04M#1 1248.78,320.55 r90 top
Z3 "2.1pF" C1608X06L-C1005X04M#2 1307.83,112.6 r270 top
Z4 "3.7nH" C1608X06L-C1005X04M#2 1248.78,112.6 r270 top
Z5 "0R" C1608X06L-C1005X04M#3 1189.74,256.36 r270 top
Z6 "3.7nH" C1608X06L-C1005X04M#3 1165.71,319.37 r180 top
Z7 "0R" C1608X06L-C1005X04M#3 1189.72,382.36 r270 top
Z9 "0.3pF" C1608X06L-C1005X04M#4 1871.06,206.69 r90 top
Z10 "12nH" C1608X06L-C1005X04M#4 1919.29,206.69 r90 top
Z11 "N.C." C1608X06L-C1005X04M#4 1871.06,1131.89 r90 top
Z12 "N.C." C1608X06L-C1005X04M#4 1919.29,1131.89 r90 top
Z21 "2.8nH" C1608X06L-C1005X04M#4 1393.7,1771.65 r0 top
Z22 "2.5nH" C1608X06L-C1005X04M#4 1303.15,1771.65 r180 top
Z23 "0R" C1608X06L-C1005X04M#4 1326.77,1700.79 r90 top
Z31 "3.8nH" C1608X06L-C1005X04M#4 849.41,2053.15 r0 top
Z32 "N.C." C1608X06L-C1005X04M#4 783.25,2029.13 r90 top
Z33 "6.0nH" C1608X06L-C1005X04M#4 716.2,2053.15 r0 top
Z34 "0.4pF" C1608X06L-C1005X04M#4 668.17,2007.92 r180 top
Z35 "1.8pF" C1608X06L-C1005X04M#4 692.18,1942.08 r90 top
Z36 "N.C." C1608X06L-C1005X04M#4 668.17,1874.93 r180 top
Z81 "0R" C1608X06L-C1005X04M#4 1474.69,147.64 r270 top
Z82 "0R" C1608X06L-C1005X04M#4 1524.21,147.64 r270 top

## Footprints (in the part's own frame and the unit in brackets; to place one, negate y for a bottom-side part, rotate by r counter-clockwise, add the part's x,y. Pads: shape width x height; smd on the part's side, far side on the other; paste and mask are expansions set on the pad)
"2 PIN STARPOINT" [mil]
  round 5.98 smd paste-196.85 mask-196.85: 1(8,0) 2(-8,0)
  Top Layer region: -11,3 11,3 11,-3 -11,-3
10056847-101LF [mm]
  rect 0.5x2 smd paste-0.05 mask+0.025: 1(-3.4,-4.1) 2(-2.6,-4.1) 3(-1.8,-4.1) 4(-1,-4.1) 5(-0.2,-4.1) 6(0.6,-4.1) 7(1.4,-4.1) 8(2.2,-4.1) 9(3,-4.1) 10(3.8,-4.1) 11(3.4,4.1) 12(2.6,4.1) 13(1.8,4.1) 14(1,4.1) 15(0.2,4.1) 16(-0.6,4.1) 17(-1.4,4.1) 18(-2.2,4.1) 19(-3,4.1) 20(-3.8,4.1)
  round 1.55 hole 1.55 unplated mask+0: ""(-4.8,0) ""(4.8,0)
  silkscreen extent -5.5,-3.9 5.5,3.9, body extent -5.5,-4.5 5.5,4.53, height 5.28
AYZ0102AGRLC [mm] "Slide Switches - SPDT, SMD, ON-ON"
  round 0.85 hole 0.85 unplated: 0(-1.5,0) 0(1.5,0)
  rect 1x1.2 smd: 1(-2.5,2.6) 2(0,2.6) 3(2.5,2.6)
  silkscreen extent -3.6,-2.5 3.6,1.5, body extent -3.6,-2.5 3.6,2.8, height 1.5
BGA4C40P2X2_76X76X62 [mm] "BGA, 4-Leads, Body 0.8x0.8mm,  Pitch 0.40mm"
  round 0.235 smd mask+0.04: A1(-0.2,0.2) A2(0.2,0.2) B1(-0.2,-0.2) B2(0.2,-0.2)
  silkscreen extent -0.74,-0.45 0.45,0.74, body extent -0.39,-0.39 0.4,0.4, height 0.55
BGA8C50P2X4_89X189X50 [mm] "BGA, 8-Leads, Body 0,89x1,89mmx0,50mm, Pitch 0,50mm"
  round 0.17 smd: A1(-0.25,0.75) A2(0.25,0.75) B1(-0.25,0.25) B2(0.25,0.25) C1(-0.25,-0.25) C2(0.25,-0.25) D1(-0.25,-0.75) D2(0.25,-0.75)
  silkscreen extent -0.6,1 -0.5,1.1, body extent -0.45,-0.94 0.45,0.94, height 0.5
BGA9C40P3X3_128X128X54 [mm] "BGA, 9-Leads, Body 1,28x1,28mmx0,54mm, Pitch 0,40mm"
  round 0.22 smd: A1(-0.4,0.4) A2(0,0.4) A3(0.4,0.4) B1(-0.4,0) B2(0,0) B3(0.4,0) C1(-0.4,-0.4) C2(0,-0.4) C3(0.4,-0.4)
  silkscreen extent -0.79,0.7 -0.7,0.79, body extent -0.64,-0.64 0.64,0.64, height 0.54
BGA32C50P6X8_350X400X50 [mm] "BGA, 32-Leads, Body 3.50x4.00mmx0.50mm, Pitch 0.50mm"
  round 0.25 smd: A1(-1.25,1.75) A2(-0.75,1.75) A5(0.75,1.75) A6(1.25,1.75) B1(-1.25,1.25) B2(-0.75,1.25) B5(0.75,1.25) B6(1.25,1.25) C3(-0.25,0.75) C4(0.25,0.75) D1(-1.25,0.25) D2(-0.75,0.25) D3(-0.25,0.25) D4(0.25,0.25) D5(0.75,0.25) D6(1.25,0.25) E1(-1.25,-0.25) E2(-0.75,-0.25) E3(-0.25,-0.25) E4(0.25,-0.25) E5(0.75,-0.25) E6(1.25,-0.25) F3(-0.25,-0.75) F4(0.25,-0.75) G1(-1.25,-1.25) G2(-0.75,-1.25) G5(0.75,-1.25) G6(1.25,-1.25) H1(-1.25,-1.75) H2(-0.75,-1.75) H5(0.75,-1.75) H6(1.25,-1.75)
  silkscreen extent -2.18,-2.08 1.83,2.44, body extent -1.75,-2 1.75,2, height 0.5
BGA45C40P5X9_217X364X49 [mm] "BGA, 45-Leads, Body 2.17x3.64mmx0.49mm, Pitch 0.40mm"
  round 0.22 smd mask+0.05: A1(-0.84,1.56) A2(-0.42,1.56) A3(0,1.56) A4(0.42,1.56) A5(0.84,1.56) B1(-0.84,1.17) B2(-0.42,1.17) B3(0,1.17) B4(0.42,1.17) B5(0.84,1.17) C1(-0.84,0.78) C2(-0.42,0.78) C3(0,0.78) C4(0.42,0.78) C5(0.84,0.78) D1(-0.84,0.39) D2(-0.42,0.39) D3(0,0.39) D4(0.42,0.39) D5(0.84,0.39) E1(-0.84,0) E2(-0.42,0) E3(0,0) E4(0.42,0) E5(0.84,0) F1(-0.84,-0.39) F2(-0.42,-0.39) F3(0,-0.39) F4(0.42,-0.39) F5(0.84,-0.39) G1(-0.84,-0.78) G2(-0.42,-0.78) G3(0,-0.78) G4(0.42,-0.78) G5(0.84,-0.78) H1(-0.84,-1.17) H2(-0.42,-1.17) H3(0,-1.17) H4(0.42,-1.17) H5(0.84,-1.17) J1(-0.84,-1.56) J2(-0.42,-1.56) J3(0,-1.56) J4(0.42,-1.56) J5(0.84,-1.56)
  silkscreen extent -1.39,-1.91 1.21,2.13, body extent -1.14,-1.85 1.14,1.84, height 0.41
BGA95C35P12X11_437X397X50 [mm] "BGA, 95-Leads, Body 4.37x3.97mmx0.50mm, Pitch 0.35mm"
  round 0.17 smd mask+0.05: A1(-1.925,1.75) A2(-1.575,1.75) A3(-1.225,1.75) A5(-0.525,1.75) A7(0.175,1.75) A9(0.875,1.75) A11(1.575,1.75) A12(1.925,1.75) B1(-1.925,1.4) B2(-1.575,1.4) B4(-0.875,1.4) B5(-0.525,1.4) B6(-0.175,1.4) B7(0.175,1.4) B8(0.525,1.4) B9(0.875,1.4) B10(1.225,1.4) B11(1.575,1.4) B12(1.925,1.4) C2(-1.575,1.05) C4(-0.875,1.05) C5(-0.525,1.05) C6(-0.175,1.05) C7(0.175,1.05) C8(0.525,1.05) C9(0.875,1.05) C10(1.225,1.05) C11(1.575,1.05) D1(-1.925,0.7) D2(-1.575,0.7) D10(1.225,0.7) D11(1.575,0.7) D12(1.925,0.7) E2(-1.575,0.35) E3(-1.225,0.35) E4(-0.875,0.35) E5(-0.525,0.35) E6(-0.175,0.35) E7(0.175,0.35) E8(0.525,0.35) E10(1.225,0.35) E11(1.575,0.35) F1(-1.925,0) F2(-1.575,0) F3(-1.225,0) F5(-0.525,0) F6(-0.175,0) F7(0.175,0) F8(0.525,0) F10(1.225,0) F11(1.575,0) F12(1.925,0) G2(-1.575,-0.35) G3(-1.225,-0.35) G5(-0.525,-0.35) G6(-0.175,-0.35) G7(0.175,-0.35) G8(0.525,-0.35) G10(1.225,-0.35) G11(1.575,-0.35) H1(-1.925,-0.7) H2(-1.575,-0.7) H3(-1.225,-0.7) H10(1.225,-0.7) H11(1.575,-0.7) H12(1.925,-0.7) J2(-1.575,-1.05) J3(-1.225,-1.05) J4(-0.875,-1.05) J5(-0.525,-1.05) J6(-0.175,-1.05) J7(0.175,-1.05) J8(0.525,-1.05) J9(0.875,-1.05) J10(1.225,-1.05) J11(1.575,-1.05) K1(-1.925,-1.4) K2(-1.575,-1.4) K3(-1.225,-1.4) K4(-0.875,-1.4) K5(-0.525,-1.4) K6(-0.175,-1.4) K7(0.175,-1.4) K8(0.525,-1.4) K9(0.875,-1.4) K10(1.225,-1.4) K11(1.575,-1.4) K12(1.925,-1.4) L1(-1.925,-1.75) L3(-1.225,-1.75) L5(-0.525,-1.75) L7(0.175,-1.75) L9(0.875,-1.75) L11(1.575,-1.75) L12(1.925,-1.75)
  silkscreen extent -2.38,-1.93 2.26,2.31, body extent -2.13,-1.93 2.26,2.06, height 0.41
BME680 [mm]
  rect 0.4x0.4 smd mask+0.1: 1(1.2,1.2) 2(1.2,0.4) 3(1.2,-0.4) 4(1.2,-1.2) 5(-1.2,-1.2) 6(-1.2,-0.4) 7(-1.2,0.4) 8(-1.2,1.2)
  silkscreen extent -1.58,-1.58 1.82,1.83, body extent -1.5,-1.5 1.5,1.5, height 0.93
BMI270 [mm] "Description 6-axis, smart, low-power, inertial measurement unit"
  rect 0.475x0.25 smd: 1(-1.162,0.75) 2(-1.162,0.25) 3(-1.162,-0.25) 4(-1.162,-0.75) 8(1.162,-0.75) 9(1.162,-0.25) 10(1.162,0.25) 11(1.162,0.75)
  rect 0.25x0.475 smd: 5(-0.5,-0.913) 6(0,-0.913) 7(0.5,-0.913) 12(0.5,0.913) 13(0,0.913) 14(-0.5,0.913)
  silkscreen extent -1.76,-1.25 1.5,1.51, body extent -1.5,-1.25 1.5,1.25, height 0.7
BT-XTAL_1612 [mm] "Crystal 1.6 x 1.2 mm"
  rect 0.65x0.55 smd: 1(-0.575,-0.425) 2(0.575,-0.425) 3(0.575,0.425) 4(-0.575,0.425)
  silkscreen extent -0.88,-0.68 0.88,0.68, body extent -0.83,-0.63 0.83,0.63, height 0.41
BT-XTAL_2016 [mm] "Crystal 2.0 x 1.6 mm"
  rect 0.95x0.85 smd: 1(-0.725,-0.575) 2(0.725,-0.575) 3(0.725,0.575) 4(-0.725,0.575)
  silkscreen extent -1.08,-0.88 1.08,0.88, body extent -1.05,-0.85 1.05,0.85, height 0.56
C1608X06L-C1005X04M#1 [mm] "Chip Capacitor, 2-Leads, Body 1.6x0.8mm, IPC High Density"
  rect 1x1 smd: 1(-0.64,0)
  rect 0.5x1 smd: 2(0.61,0)
  Mid Layer 1 keep-out region: -1.122,-0.575 1.128,-0.575 1.128,0.575 -1.122,0.575
  Mid Layer 2 keep-out region: -1.122,-0.575 1.128,-0.575 1.128,0.575 -1.122,0.575
  silkscreen extent -1.05,-0.5 1.05,0.5, body extent -0.8,-0.4 0.8,0.4, height 0.86
C1608X06L-C1005X04M#2 [mm] "Chip Capacitor, 2-Leads, Body 1.6x0.8mm, IPC High Density"
  rect 1x1 smd: 1(-0.642,0)
  rect 0.5x1 smd: 2(0.61,0)
  Mid Layer 1 keep-out region: -1.125,-0.578 1.125,-0.578 1.125,0.572 -1.125,0.572
  Mid Layer 2 keep-out region: -1.125,-0.578 1.125,-0.578 1.125,0.572 -1.125,0.572
  silkscreen extent -1.05,-0.5 1.05,0.5, body extent -0.8,-0.4 0.8,0.4, height 0.86
C1608X06L-C1005X04M#3 [mm] "Chip Capacitor, 2-Leads, Body 1.6x0.8mm, IPC High Density"
  rect 1x1 smd: 1(-0.61,0) 2(0.61,0)
  Mid Layer 1 keep-out region: -1.125,-0.576 1.125,-0.576 1.125,0.574 -1.125,0.574
  Mid Layer 2 keep-out region: -1.125,-0.576 1.125,-0.576 1.125,0.574 -1.125,0.574
  silkscreen extent -1.05,-0.5 1.05,0.5, body extent -0.8,-0.4 0.8,0.4, height 0.86
C1608X06L-C1005X04M#4 [mm] "Chip Capacitor, 2-Leads, Body 1.6x0.8mm, IPC High Density"
  rect 0.61x0.71 smd: 1(-0.61,0) 2(0.61,0)
  rect 0.46x0.61 smd: 1(-0.485,0) 2(0.485,0)
  Mid Layer 1 keep-out region: -1.127,-0.575 1.123,-0.575 1.123,0.575 -1.127,0.575
  Mid Layer 2 keep-out region: -1.127,-0.575 1.123,-0.575 1.123,0.575 -1.127,0.575
  silkscreen extent -1.05,-0.5 1.05,0.5, body extent -0.8,-0.4 0.8,0.4, height 0.86
CAF-50P160X80-6N [mm] "Chip Array, Flat, 6-Leads, Pitch 0,50mm,  Body 1,60x0,80mm,  IPC Medium Density"
  rect 0.5x0.25 smd mask+0.08: 1(-0.45,0.5) 2(-0.45,0) 3(-0.45,-0.5) 5(0.45,-0.5) 6(0.45,0) 7(0.45,0.5)
  Top Layer region: 1.025,0.375 0.2,0.375 0,0.175 0,-0.175 0.2,-0.375 1.025,-0.375 1.175,-0.525 1.175,-0.95 0.15,-0.95 0,-0.8 0,-0.375 -0.25,-0.125 -0.8,-0.125 -0.9,-0.225 -1,-0.225 -1,0.225 -0.9,0.225 -0.8,0.125 -0.25,0.125 0,0.375 0,0.8 0.15,0.95 1.175,0.95 1.175,0.525
  silkscreen extent -1.1,-1 1,1.02, body extent -0.5,-0.88 0.5,0.88, height 0.7
CAPC0603X03L_C [mm] "Chip Capacitor, 2-Leads, Body 0.6x0.3mm, IPC High Density"
  rect 0.27x0.3 smd mask+0.05: 1(-0.285,0) 2(0.285,0)
  silkscreen extent -0.49,-0.22 0.49,0.22, body extent -0.3,-0.15 0.31,0.15, height 0.3
CAPC0603X03L_C_NC [mm] "Chip Capacitor, 2-Leads, Body 0.6x0.3mm, IPC High Density"
  rect 0.27x0.3 smd mask+0.05: 1(-0.285,0) 2(0.285,0)
  silkscreen extent -0.49,-0.22 0.49,0.22
CAPC1005X04L [mm] "Chip Capacitor, 2-Leads, Body 1.0x0.5mm, IPC High Density"
  rect 0.6x0.5 smd: 1(-0.5,0) 2(0.5,0)
  silkscreen extent -0.9,-0.35 0.9,0.35, body extent -0.51,-0.25 0.51,0.25, height 0.5
CAPC1005X04L_C2 [mm] "Chip Capacitor, 2-Leads, Body 1.0x0.5mm, IPC High Density"
  rect 0.425x0.5 smd mask+0.05: 1(-0.463,0) 2(0.463,0)
  silkscreen extent -0.77,-0.35 0.77,0.35, body extent -0.51,-0.25 0.51,0.25, height 0.5
CAPC1608X06L [mm] "Chip Capacitor, 2-Leads, Body 1.6x0.8mm, IPC High Density"
  rect 0.75x0.8 smd: 1(-0.675,0) 2(0.675,0)
  silkscreen extent -1.17,-0.5 1.17,0.5, body extent -0.8,-0.43 0.8,0.43, height 0.8
CAPC2012X11L [mm] "Chip Capacitor, 2-Leads, Body 2.0x1.3mm, IPC High Density"
  rect 1.1x1.4 smd: 1(-0.75,0) 2(0.75,0)
  silkscreen extent -1.43,-0.8 1.42,0.8, body extent -1,-0.62 1,0.63, height 0.77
